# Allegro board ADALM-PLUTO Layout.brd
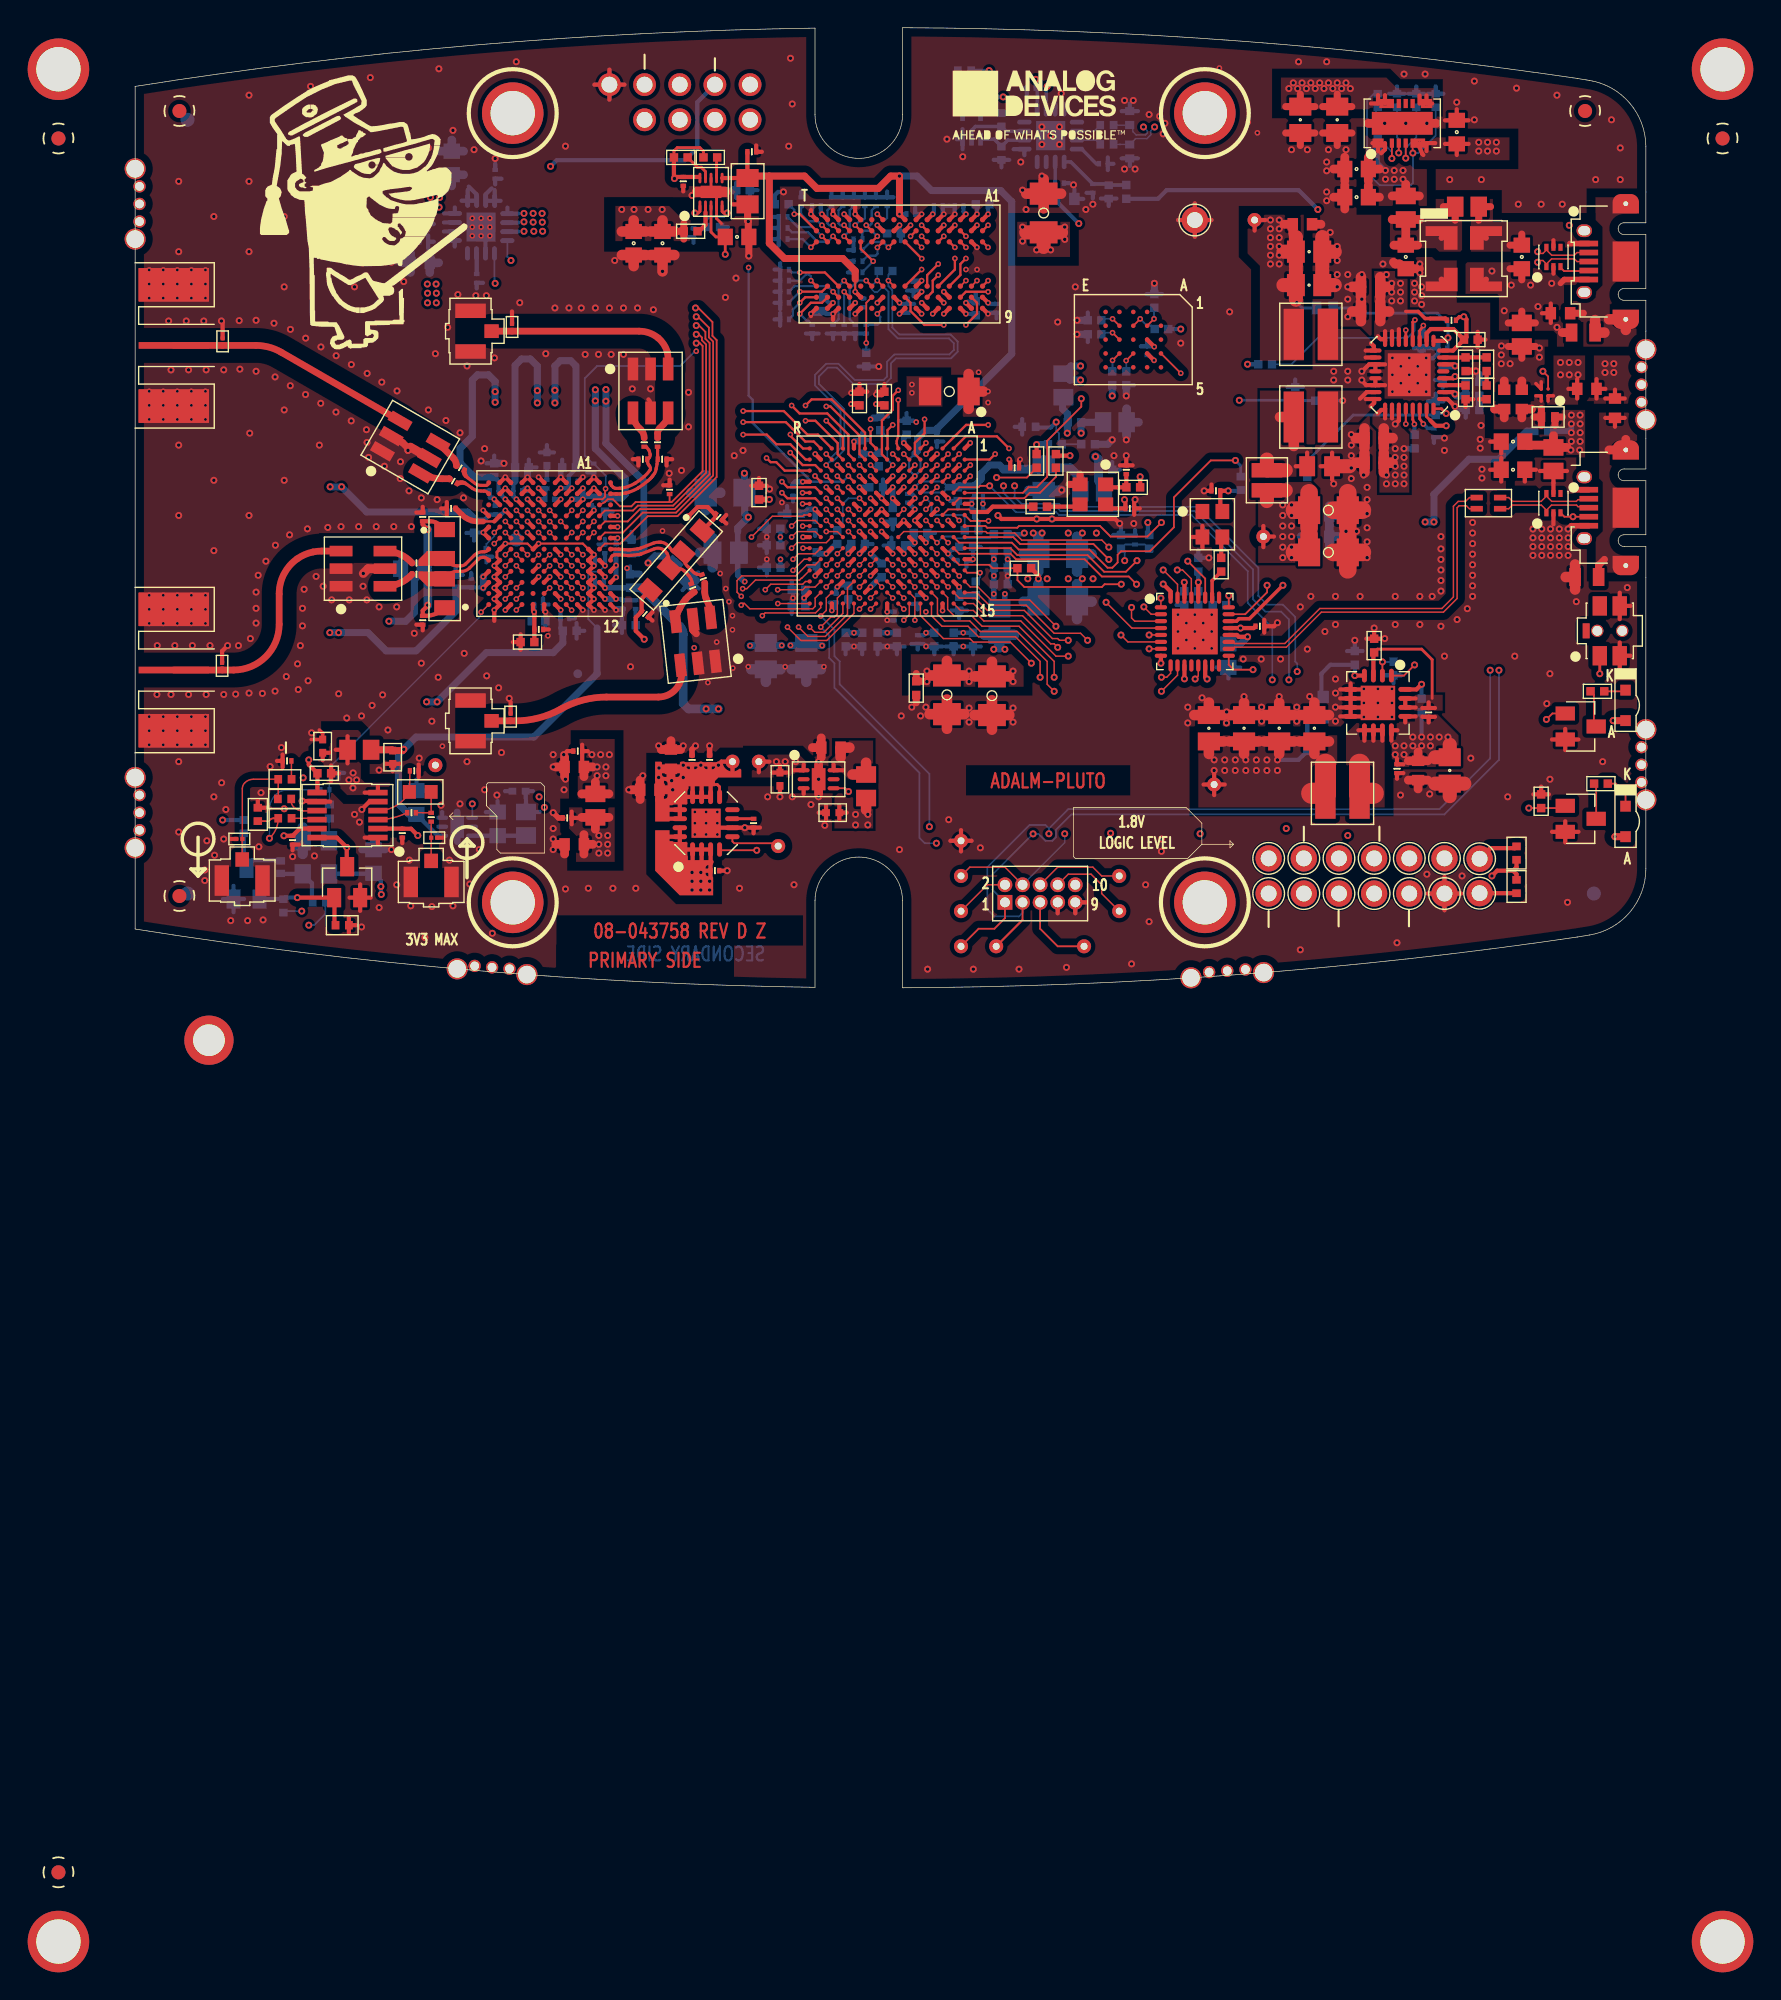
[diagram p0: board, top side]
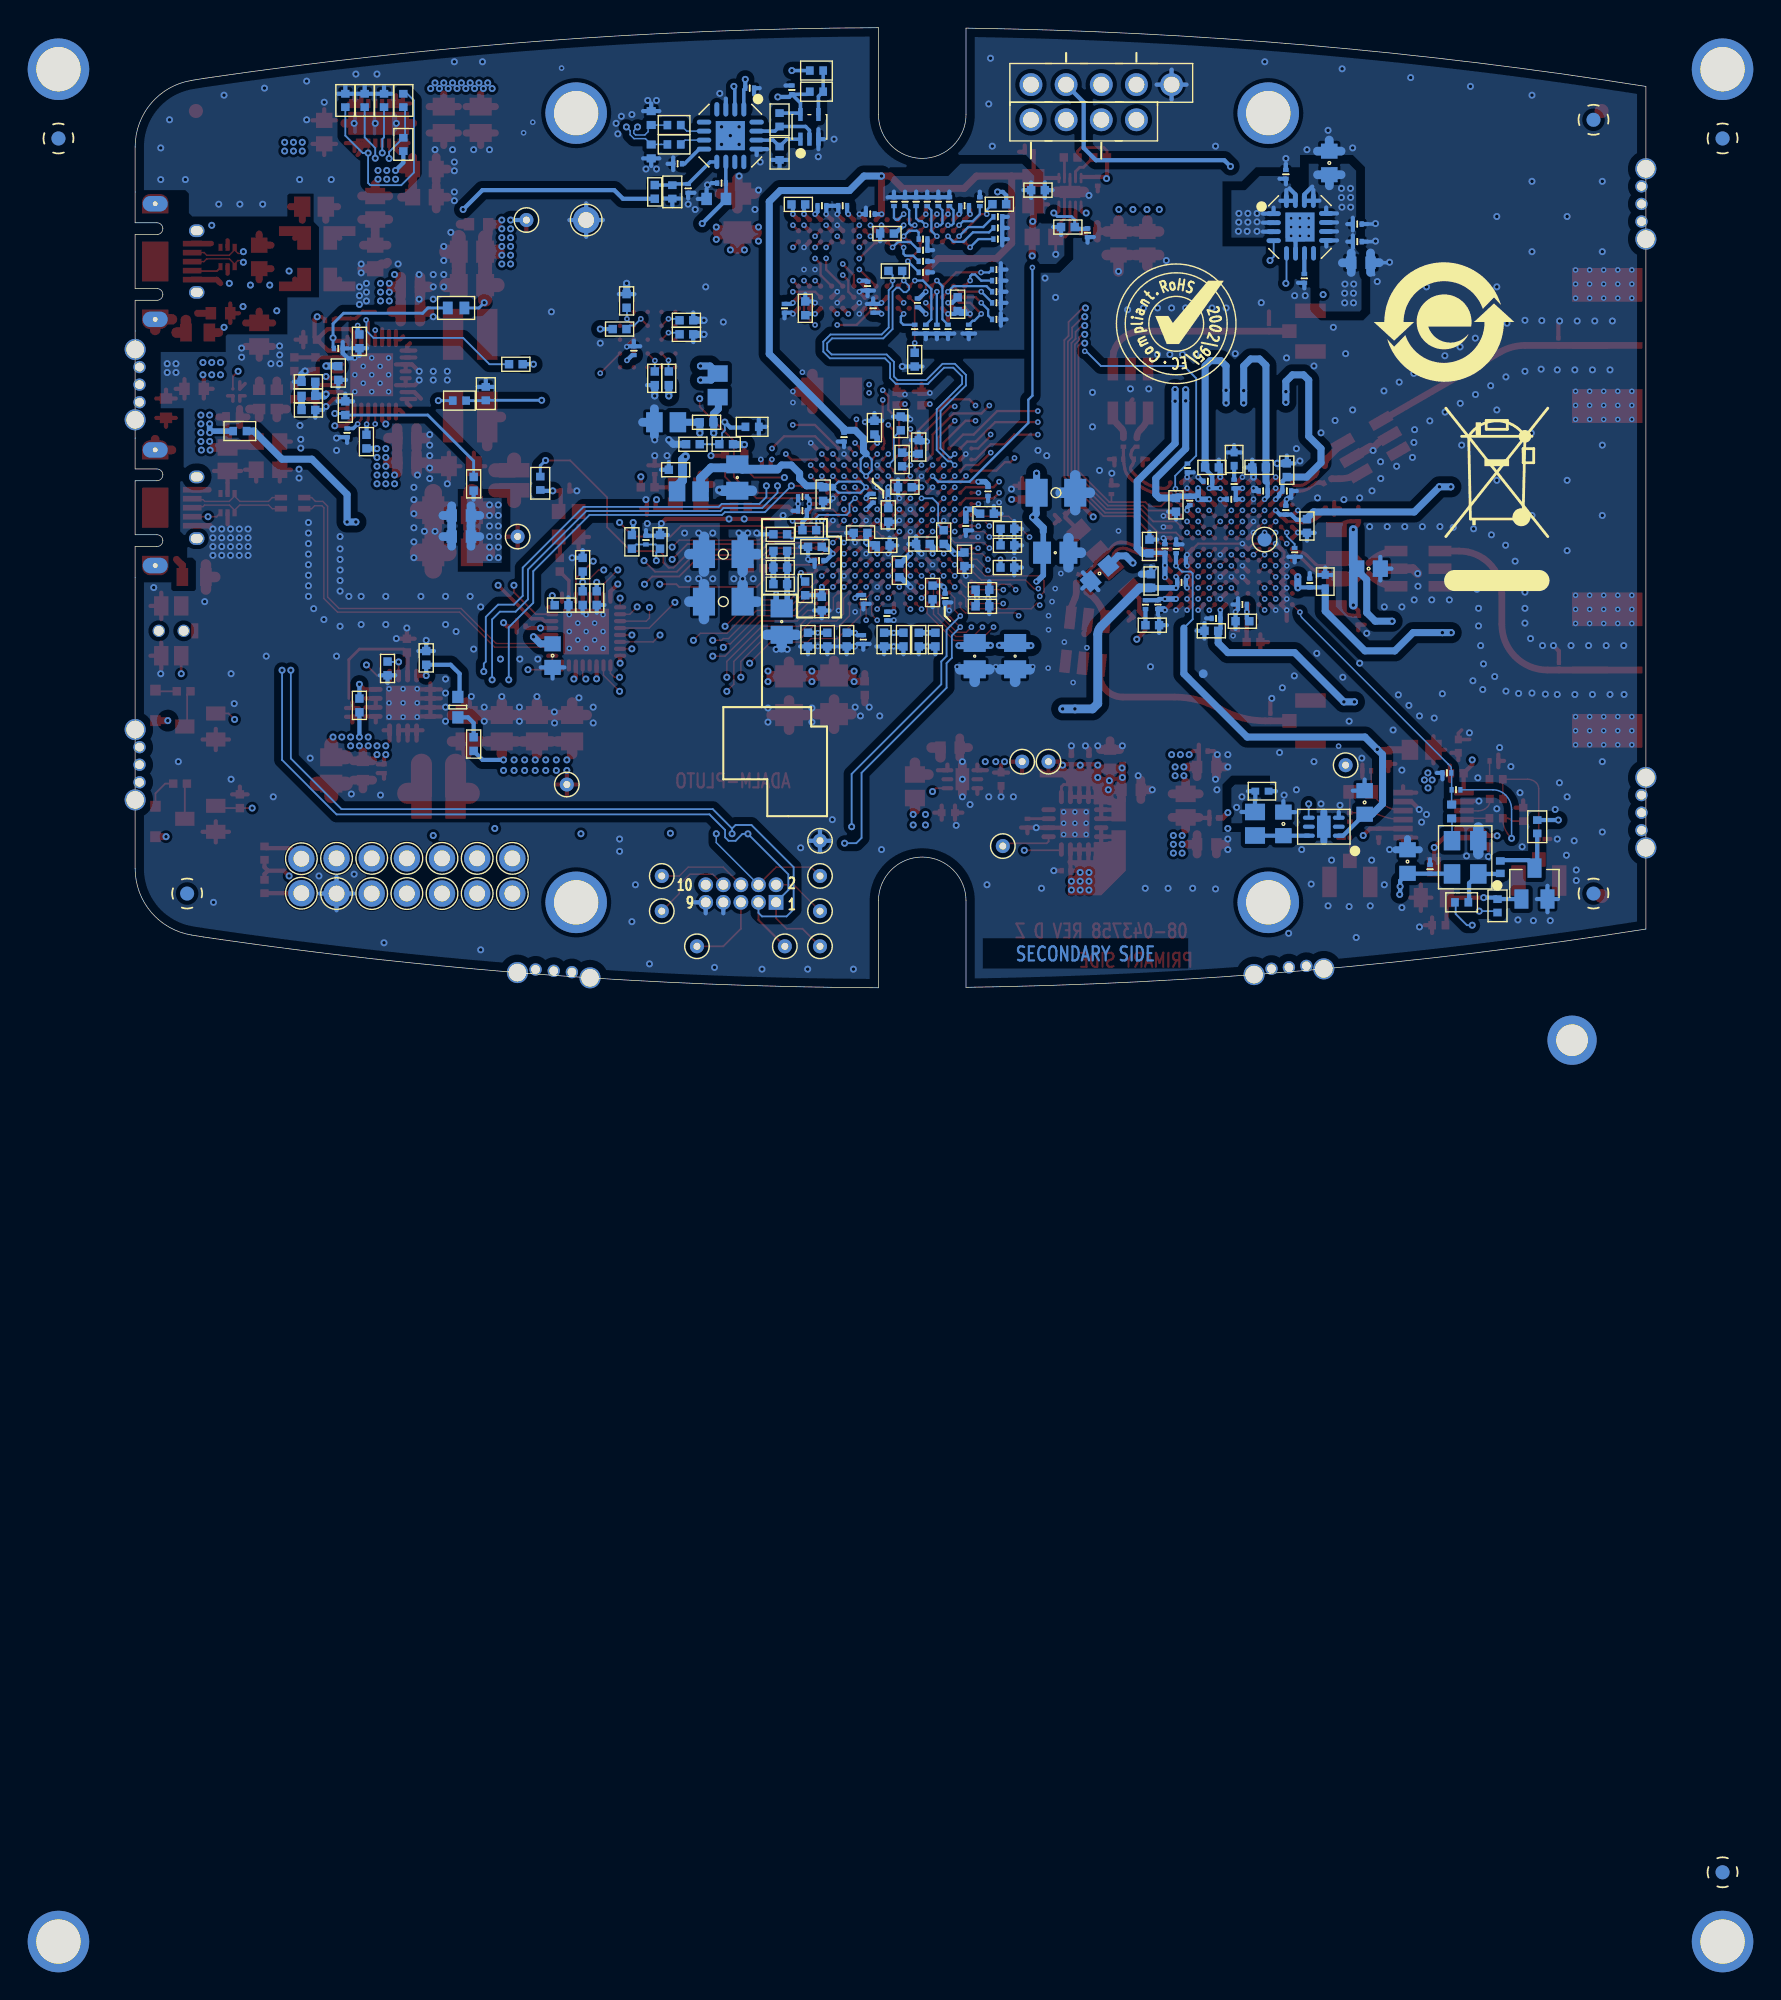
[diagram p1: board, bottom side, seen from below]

Outline 109.14 x 69.34 mm; copper layers: TOP, L2_GND, L3_PWR, L4_GND, L5_SIG, L6_SIG, L7_GND, L8_PWR, L9_GND, BOTTOM. Coordinates in mm from the lower left corner of the outline.
Outline path: 0,65.1 arc(24.48,68.08) 49.11,69.31 49.11,63.06 arc(52.28,59.9) 55.44,63.06 55.44,69.34 arc(79.87,68.37) 104.18,65.67 105.05,65.53 arc(107.98,63.88) 109.14,60.73 109.14,57.47 109.14,55.25 107.56,55.25 arc(107.26,55.12) 107.14,54.82 arc(107.26,54.52) 107.56,54.4 109.14,54.4 109.14,50.5 107.56,50.5 arc(107.26,50.37) 107.14,50.07 arc(107.26,49.77) 107.56,49.65 109.14,49.65 109.14,37.47 107.56,37.47 arc(107.26,37.34) 107.14,37.04 arc(107.26,36.74) 107.56,36.62 109.14,36.62 109.14,32.72 107.56,32.72 arc(107.26,32.59) 107.14,32.29 arc(107.26,31.99) 107.56,31.87 109.14,31.87 109.14,29.65 109.14,8.61 arc(107.98,5.45) 105.05,3.81 104.18,3.67 arc(79.87,0.97) 55.44,0 55.44,6.28 arc(52.28,9.44) 49.11,6.28 49.11,0.03 arc(24.48,1.26) 0,4.24 0,65.1

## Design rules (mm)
constraint set DEFAULT: min track width 0.127
net group DDR3_CK: nets DDR3_CK_N DDR3_CK_P
net group DDR3_DQS0: nets DDR3_DQS0_N DDR3_DQS0_P
net group DDR3_DQS1: nets DDR3_DQS1_N DDR3_DQS1_P
net group DP1: nets UNNAMED_9_CHOKE4P_I350_N2 UNNAMED_9_CHOKE4P_I350_N3
net group RX1A: nets RX1A_N RX1A_P
net group RX2A: nets RX2A_N RX2A_P
net group TX1A: nets TX1A_N TX1A_P
net group TX2A: nets TX2A_N TX2A_P
net group UART: nets UART_RX UART_TX
net group USB_OTG: nets USB_OTG_N USB_OTG_P
net group USB_UART: nets USB_UART_N USB_UART_P
net group CTRL_IN: nets CTRL_IN0 CTRL_IN1 CTRL_IN2 CTRL_IN3
net group CTRL_OUT: nets IO_L08_34_CTRL_OUT0 IO_L08_34_CTRL_OUT1 IO_L13_34_CTRL_OUT2 IO_L13_34_CTRL_OUT3 IO_L21_34_CTRL_OUT4 IO_L21_34_CTRL_OUT5 IO_L22_34_CTRL_OUT6 IO_L22_34_CTRL_OUT7
net group JTAG: nets JTAG_TCK JTAG_TDI JTAG_TDO JTAG_TMS
net group PWR: nets VCCPLL VDD33_USB VDDA1P1_RX_VCO VTTVREF
net group QSPI: nets PS_MIO01_500_QSPI0_SS_B PS_MIO02_500_QSPI0_IO0 PS_MIO03_500_QSPI0_IO1 PS_MIO04_500_QSPI0_IO2 PS_MIO05_500_QSPI0_IO3 PS_MIO06_500_QSPI0_SCLK
net group RF: nets UNNAMED_7_CAP_I57_N2 UNNAMED_7_CAP_I58_N2 UNNAMED_7_CAP_I85_N1 UNNAMED_7_CAP_I86_N1 UNNAMED_7_CAP_I116_N1 UNNAMED_7_CAP_I117_N1 UNNAMED_7_CAP_I118_N2 UNNAMED_7_CAP_I119_N2 UNNAMED_7_CNBNC3P_I43_CNTR UNNAMED_7_CNBNC3P_I74_CNTR UNNAMED_7_CNBNC5P_I64_CNTR UNNAMED_7_CNBNC5P_I83_CNTR
net group RX: nets IO_L01_34_RX_D0 IO_L01_34_RX_D1 IO_L02_34_RX_D2 IO_L02_34_RX_D3 IO_L03_34_RX_D4 IO_L03_34_RX_D5 IO_L04_34_RX_D6 IO_L04_34_RX_D7 IO_L05_34_RX_D8 IO_L05_34_RX_D9 IO_L06_34_RX_D10 IO_L06_34_RX_D11 IO_L07_34_RX_FRAME IO_L12_MRCC_34_DATA_CLK
net group SPI: nets IO_L23_35_SPI_CLK IO_L23_35_SPI_ENB IO_L24_35_SPI_DI IO_L24_35_SPI_DO
net group TX: nets IO_L01_34_FB_CLK IO_L09_34_TX_FRAME IO_L15_34_TX_D0 IO_L15_34_TX_D1 IO_L16_34_TX_D2 IO_L16_34_TX_D3 IO_L17_34_TX_D4 IO_L17_34_TX_D5 IO_L18_34_TX_D6 IO_L18_34_TX_D7 IO_L19_34_TX_D8 IO_L19_34_TX_D9 IO_L20_34_TX_D10 IO_L20_34_TX_D11
net group USB_ULPI: nets PS_MIO28_501_USB0_D4 PS_MIO29_501_USB0_DIR PS_MIO30_501_USB0_STP PS_MIO31_501_USB0_NXT PS_MIO32_501_USB0_D0 PS_MIO33_501_USB0_D1 PS_MIO34_501_USB0_D2 PS_MIO35_501_USB0_D3 PS_MIO36_501_USB0_CLK PS_MIO37_501_USB0_D5 PS_MIO38_501_USB0_D6 PS_MIO39_501_USB0_D7

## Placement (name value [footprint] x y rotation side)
AD9361_CLKOUT  TESTPAD  [TPSMC40]  27.55 32.37 180 bottom
ADC  613 001 111 21  [CNHDR1X1H344]  44.42 65.22 180 bottom
C1  0.1uF  [C0201]  26.01 58.75 89.8 bottom
C2  0.01uF  [C0201]  24.67 51.23 269.8 bottom
C3  10uF  [C0603#2]  22.87 59.57 89.8 bottom
C4  10uF  [C0603]  20.59 52.36 179.8 bottom
C5  0.1uF  [C0201]  20.85 53.88 179.8 bottom
C6  0.1uF  [C0201]  20.85 55.15 179.8 bottom
C7  0.1uF  [C0201]  93.83 40.08 90 bottom
C8  0.1uF  [C0201]  91.16 15.82 270 top
C9  10uF  [C0603]  92.68 15.69 270 top
C10  0.1uF  [C0201]  41.88 8.46 0 top
C11  47uF  [C0805H60]  94.97 15.69 270 top
C12  0.01uF  [C0201]  44.68 11.88 270 top
C13  0.1uF  [C0201#2]  89.51 24.71 90 top
C14  10uF  [C0603]  38.71 16.51 90 top
C15  10uF  [C0603]  37.18 14.3 180 top
C16  0.1uF  [C0201]  40.23 16.46 90 top
C17  47uF  [C0805H60]  82.65 18.74 90 top
C18  0.1uF  [C0201]  41.5 16.46 90 top
C19  47uF  [C0805H60]  77.57 18.74 90 top
C20  47uF  [C0805H60]  80.11 18.74 90 top
C21  47uF  [C0805H60]  85.19 18.74 90 top
C22  10uF  [C0603]  31.72 10.36 180 top
C23  0.01uF  [C0201]  31.65 36.58 0 bottom
C24  0.01uF  [C0201]  25.94 35.88 180 bottom
C25  0.1uF  [C0201]  31.21 12.27 180 top
C26  0.01uF  [C0201]  31.05 26.68 0 bottom
C27  0.01uF  [C0201]  34.75 31.72 90 bottom
C28  1UF  [C0402H22]  31.35 37.58 180 bottom
C29  1UF  [C0402H22]  25.94 37.38 90 bottom
C30  1UF  [C0402H22]  31.39 25.78 0 bottom
C31  1UF  [C0402H22]  35.86 31.87 90 bottom
C32  10uF  [C0603]  31.72 15.95 180 top
C33  0.1uF  [C0201]  31.98 17.09 180 top
C34  1UF  [C0402H22]  27.94 37.58 0 bottom
C35  1UF  [C0402H22]  35.75 29.38 90 bottom
C36  1UF  [C0402H22]  24.48 33.35 270 bottom
C37  1UF  [C0402H22]  33.95 34.88 270 bottom
C38  1UF  [C0402H22]  29.15 26.47 0 bottom
C39  0.01uF  [C0201]  27.64 35.88 0 bottom
C40  0.01uF  [C0201]  33.54 29.28 180 bottom
C41  0.01uF  [C0201]  26.01 34.49 90 bottom
C42  0.01uF  [C0201]  32.95 35.18 270 bottom
C43  0.01uF  [C0201]  29.16 25.88 0 top
C44  0.01uF  [C0201]  29.15 27.68 0 bottom
C45  1UF  [C0402H22]  28.34 24.97 180 top
C46  0.1uF  [C0201]  71.85 34.62 0 top
C47  0.1uF  [C0201]  72.24 32.33 90 bottom
C48  0.1uF  [C0201]  73.11 46.01 90 bottom
C49  100uF  [C1206H71]  66.65 31.32 0 bottom
C50  4.7uF  [C0402]  62.53 31.55 0 bottom
C51  0.47uF  [C0402]  47.6 34.24 180 bottom
C52  0.1uF  [C0201]  60.93 35.45 0 bottom
C53  0.01uF  [C0201]  60.93 34.45 0 bottom
C54  100uF  [C1206H71]  58.82 43.06 0 top
C55  4.7uF  [C0402]  55.73 40.45 90 bottom
C56  0.47uF  [C0402]  45.07 35.76 90 top
C57  0.47uF  [C0402]  54.13 42.55 90 top
C58  0.47uF  [C0402]  52.33 42.55 90 top
C59  0.47uF  [C0402]  52.53 39.05 90 bottom
C60  0.1uF  [C0201]  63.54 37.56 0 top
C61  0.01uF  [C0201]  47.52 35.85 270 bottom
C62  0.01uF  [C0201]  39.6 58.24 90 top
C63  0.01uF  [C0201]  56.03 55.88 180 bottom
C64  100uF  [C1206H71]  61.9 21.09 270 top
C65  47uF  [C0805H60]  48.49 23.95 270 bottom
C66  4.7uF  [C0402]  53.93 30.15 270 bottom
C67  4.7uF  [C0402]  52.53 25.14 270 bottom
C68  0.47uF  [C0402]  56.43 21.64 270 top
C69  0.47uF  [C0402]  60.03 31.85 0 bottom
C70  0.47uF  [C0402]  54.73 34.15 270 bottom
C71  100uF  [C1206H71]  58.65 21.16 270 top
C72  0.47uF  [C0402]  52.23 32.05 0 bottom
C73  4.7uF  [C0402]  53.53 36.15 0 bottom
C74  0.47uF  [C0402]  55.13 31.95 180 bottom
C75  0.47uF  [C0402]  56.73 32.85 0 bottom
C76  100uF  [C1206H71]  42.62 35.75 180 bottom
C77  47uF  [C0805H60]  42.67 31.42 180 bottom
C78  4.7uF  [C0402]  46.12 31.95 180 bottom
C79  10uF  [C0603#2]  43.48 54.23 0 top
C80  0.01uF  [C0201]  40.33 54.53 270 bottom
C81  0.22UF  [C0805H53]  44.25 57.53 270 top
C82  10uF  [C0603#2]  36.02 53.77 270 top
C83  10uF  [C0603#2]  38.1 53.77 270 top
C84  0.01uF  [C0201]  44.55 60.37 0 top
C85  47uF  [C0805H60]  65.64 36.85 270 bottom
C86  4.7uF  [C0402]  49.72 49.37 270 bottom
C87  4.7uF  [C0402]  60.73 49.07 90 bottom
C88  0.47uF  [C0402]  61.23 56.58 180 bottom
C89  0.47uF  [C0402]  54.82 54.47 0 bottom
C90  0.47uF  [C0402]  46.12 33.15 180 bottom
C91  0.1uF  [C0201]  55.82 49.07 90 bottom
C92  0.1uF  [C0201]  56.22 50.67 270 bottom
C93  0.47uF  [C0402]  67.86 40.84 0 bottom
C94  0.1uF  [C0201]  59.52 56.48 180 bottom
C95  0.1uF  [C0201]  58.02 56.48 0 bottom
C96  0.1uF  [C0201]  49.22 56.47 180 bottom
C97  0.1uF  [C0201]  62.23 49.07 270 bottom
C98  0.1uF  [C0201]  55.83 35.35 90 bottom
C99  0.01uF  [C0201]  57.92 39.76 90 bottom
C100  100uF  [C1206H71]  65.63 55.95 90 top
C101  4.7uF  [C0402]  43.91 57.6 180 bottom
C102  0.01uF  [C0201]  52.62 49.47 270 bottom
C103  47uF  [C0805H60]  62.43 26.44 270 bottom
C104  47uF  [C0805H60]  45.57 23.95 270 bottom
C105  4.7uF  [C0402]  55.03 25.14 270 bottom
C106  4.7uF  [C0402]  51.33 25.14 270 bottom
C107  4.7uF  [C0402]  60.53 25.14 270 bottom
C108  4.7uF  [C0402]  46.13 30.35 180 bottom
C109  0.47uF  [C0402]  53.63 25.14 270 bottom
C110  0.47uF  [C0402]  51.53 28.55 270 bottom
C111  0.47uF  [C0402]  59.53 27.74 270 bottom
C112  0.47uF  [C0402]  47.93 28.75 180 bottom
C113  0.47uF  [C0402]  59.13 25.14 270 bottom
C114  0.47uF  [C0402]  47.93 27.55 180 bottom
C115  0.47uF  [C0402]  57.74 25.14 270 bottom
C116  0.47uF  [C0402]  49.22 30.95 270 bottom
C117  0.1uF  [C0201]  56.53 25.14 270 bottom
C118  0.1uF  [C0201]  50.63 28.15 270 bottom
C119  0.01uF  [C0201]  54.83 26.85 270 bottom
C120  0.01uF  [C0201]  49.13 33.35 270 bottom
C121  10uF  [C0603#2]  17.22 9.12 90 bottom
C122  0.1uF  [C0201]  15.59 8.56 90 bottom
C123  1UF  [C0402H22]  27.74 14.2 180 bottom
C124  18PF  [C0201]  14.37 15.52 0 bottom
C125  0.001uF  [C0201]  29.94 35.28 180 bottom
C126  1UF  [C0402H22]  29.74 38.18 270 bottom
C127  1UF  [C0402H22]  35.66 26.18 179.9 bottom
C128  0.001uF  [C0201]  35.25 27.67 270 bottom
C129  0.001uF  [C0201]  20.78 26.54 90 top
C130  18PF  [C0201]  41.04 29.54 289.4 top
C131  18PF  [C0201]  20.32 29.86 180 top
C132  18PF  [C0201]  20.32 30.67 180 top
C133  18PF  [C0201]  22.98 36.59 330 top
C134  18PF  [C0201]  23.49 37.55 330 top
C135  10uF  [C0603]  89.51 39.7 180 top
C136  10uF  [C0603]  89.25 48.84 180 top
C137  10uF  [C0603]  89.51 37.92 180 top
C138  10uF  [C0603]  89.25 50.62 180 top
C139  0.047UF  [C0402]  92.94 46.68 90 bottom
C140  1UF  [C0402H22]  76.81 30.55 90 bottom
C141  1UF  [C0402H22]  96.49 46.81 0 top
C142  150pF  [C0402]  96.62 43.76 180 bottom
C143  180PF  [C0402]  96.11 45.03 90 top
C144  0.0033uF  [C0402]  97.64 45.03 270 top
C145  47uF  [C0805H60]  84.81 53.16 0 top
C146  22UF  [C0805]  85.57 37.67 0 top
C147  5.6NF  [C0402H22]  96.62 41.73 0 bottom
C148  47uF  [C0805H60]  84.81 50.75 0 top
C149  100uF  [C1206H71]  86.21 31.44 0 top
C150  100uF  [C1206H71]  86.21 34.49 0 top
C151  10uF  [C0603]  84.33 55.14 0 top
C152  10uF  [C0603]  85.57 34.11 0 bottom
C153  10uF  [C0603]  85.57 32.59 0 bottom
C154  1UF  [C0402H22]  75.79 28.14 270 bottom
C155  10uF  [C0603#2]  20.03 30.27 180 bottom
C156  18PF  [C0201]  40.28 28.88 290.2 top
C157  18PF  [C0201]  13.71 14.3 0 bottom
C158  100uF  [C1206H71]  66.65 27.89 0 bottom
C159  4.7uF  [C0402]  62.53 30.35 0 bottom
C160  0.47uF  [C0402]  62.53 29.15 0 bottom
C161  0.1uF  [C0201]  56.53 28.05 270 bottom
C162  0.01uF  [C0201]  59.73 30.85 0 bottom
C163  0.1uF  [C0201]  78.08 35.89 0 top
C164  0.1uF  [C0201]  81.25 26.11 0 top
C165  2.2UF  [C0603#2]  78.98 23.99 270 bottom
C166  0.001uF  [C0201]  42.16 34.01 139 top
C167  10uF  [C0603#2]  39.47 29.92 318.8 bottom
C168  1UF  [C0402H22]  76.81 28.14 270 bottom
C169  1UF  [C0402H22]  50.39 12.65 180 top
C170  1UF  [C0402H22]  46.58 15.06 270 top
C171  2.2UF  [C0603]  98.91 42.49 90 top
C172  2.2UF  [C0603]  100.18 42.49 90 top
C173  10uF  [C0603]  50.26 17.35 180 top
C174  4.7uF  [C0402]  70.09 37.41 0 bottom
C175  18PF  [C0201]  36.78 39.39 270 top
C176  18PF  [C0201]  37.74 39.39 270 top
C177  0.1UF  [C0603]  106.91 41.86 270 top
C178  0.47uF  [C0402]  59.44 35.65 270 bottom
C179  0.01uF  [C0201]  21.39 12.32 90 top
C180  0.01uF  [C0201]  20.17 15.67 0 top
C181  0.1UF  [C0603]  102.97 48.71 0 top
C182  2.2UF  [C0603]  104.87 43.25 0 top
C183  0.1UF  [C0603#2]  99.54 39.44 180 top
C184  47uF  [C0805H60]  86.84 62.68 270 top
C185  47uF  [C0805H60]  84.17 62.68 270 top
C186  0.1uF  [C0201]  64.74 64.97 180 bottom
C187  0.01uF  [C0201]  69.19 57.73 270 bottom
C188  0.1uF  [C0201]  66.77 58.11 0 bottom
C189  0.1uF  [C0201]  69.95 59.51 0 bottom
C190  0.1uF  [C0201]  61.69 64.84 90 bottom
C191  0.01uF  [C0201]  24.28 29.23 90 bottom
C192  1UF  [C0402H22]  23.16 29.33 90 bottom
C193  0.001uF  [C0201]  36.83 27 138.4 top
C194  0.001uF  [C0201]  20.78 34.01 270 top
C195  10uF  [C0603#2]  26.19 11.83 90 bottom
C196  47pF  [C0402]  71.85 60.4 90 bottom
C197  47pF  [C0402]  71.85 62.81 270 bottom
C198  2.2UF  [C0603#2]  20.32 13.38 90 bottom
C199  1UF  [C0402H22]  18.61 16.65 270 top
C200  1UF  [C0402H22]  13.55 17.45 90 top
C201  0.1uF  [C0201]  11.37 10.66 270 top
C202  0.1uF  [C0201]  19.3 11.17 270 top
C203  0.1uF  [C0201]  33.93 31.7 90 bottom
C204  47pF  [C0402]  14.03 12.73 90 bottom
C205  0.01uF  [C0201]  10.97 16.38 180 top
C206  0.1uF  [C0201]  38.61 35.97 90 top
C207  0.001uF  [C0201]  25.37 31.44 90 bottom
C208  0.1uF  [C0201]  33.12 37.54 270 bottom
C209  10uF  [C0603#2]  88.24 59.13 180 top
C210  2.2UF  [C0603#2]  95.48 61.8 90 top
C211  0.1UF  [C0603#2]  99.54 37.41 180 top
C212  0.1UF  [C0603#2]  88.24 57.1 180 top
C213  0.1UF  [C0603#2]  91.79 52.78 270 top
C214  0.1UF  [C0603#2]  100.18 52.78 270 top
C215  2.2UF  [C0603]  67.16 56.97 0 bottom
CLK_IN  U.FL-R-SMT-1(01)  [CNHIROSE-U_FL-R-SMT-1]  21.39 7.64 180 top
CLK_OUT  U.FL-R-SMT-1(01)  [CNHIROSE-U_FL-R-SMT-1]  7.73 7.74 180 top
D1  SP3004-04XTG  [SOT-563]  102.46 35 0 top
D2  SP3004-04XTG  [SOT-563]  102.46 52.78 0 top
D3  ESD8472MUT5G  [DFN2_0_62X0_32]  27.23 47.72 270 top
D4  ESD8472MUT5G  [DFN2_0_62X0_32]  6.32 46.68 270 top
D7  ESD8472MUT5G  [DFN2_0_62X0_32]  21.61 10.84 180 top
D8  ESD8472MUT5G  [DFN2_0_62X0_32]  7.53 10.75 0 top
D9  ESD8472MUT5G  [DFN2_0_62X0_32]  6.28 23.25 270 top
D10  ESD8472MUT5G  [DFN2_0_62X0_32]  27.13 19.58 270 top
DAC1  613 001 111 21  [CNHDR1X1H344]  36.8 65.22 180 bottom
DAC2  613 001 111 21  [CNHDR1X1H344]  36.8 62.68 180 bottom
DS1  LTST-S220TBKT  [LED0804]  107.67 20.39 270 top
DS2  LTST-S220TBKT  [LED0804]  107.67 12.01 270 top
E1  100OHM  [L0805]  69.14 35.85 180 bottom
E2  100OHM  [L0805]  52.8 14.55 90 top
E3  600OHM AT 100MEGHZ  [L0805]  102.46 38.17 270 top
E4  100OHM  [L0805]  33.25 13.15 90 top
E5  100OHM  [L0805]  67.05 43.51 270 bottom
E6  100OHM  [L0805]  70.78 40.84 180 bottom
E7  100OHM  [L0805]  28.24 11.85 270 bottom
E8  100OHM  [L0805]  16.19 17.19 180 top
E9  600OHM AT 100MEGHZ  [L0805]  91.79 56.33 270 top
E10  600OHM AT 100MEGHZ  [L0805]  100.18 47.17 90 top
E11  600OHM AT 100MEGHZ  [L0805]  96.21 56.41 0 top
F1  0.5A  [F0402H20]  102.08 41.22 0 top
GND  613 001 111 21  [unnamed#3]  34.26 65.22 180 bottom
GND#2  WP45  [unnamed#3]  94.59 6.8 180 bottom
GND#3  WP45  [unnamed#3]  76.55 55.45 180 bottom
GND#4  TESTPAD  [unnamed#3]  59.66 10.61 180 bottom
GPO0  613 001 111 21  [CNHDR1X1H344]  44.42 62.68 180 bottom
GPO1  613 001 111 21  [CNHDR1X1H344]  41.88 62.68 180 bottom
GPO2  613 001 111 21  [CNHDR1X1H344]  39.34 62.68 180 bottom
GPO3  613 001 111 21  [CNHDR1X1H344]  39.34 65.22 180 bottom
JTAG_BOOT  TESTPAD  [TPSMC40]  68.55 2.99 180 bottom
L1  330NH  [L0805-F]  40.28 32.22 228.6 top
L2  1.5uH  [LSMSQ157H83]  84.94 47.19 180 top
L3  1.5uH  [LSMSQ157H83]  84.94 41.22 180 top
L4  1uH  [LSMSQ157H83]  87.22 14.04 180 top
L5  270NH  [LSMSQ79H41]  81.76 36.65 270 top
L6  90OHMS AT 100MEGHZ  [L0805-4PH39]  97.76 35 0 top
L7  330NH  [L0805-F]  37.9 29.51 48.8 top
L7N  WP45  [TPC75D45]  97.13 9.32 0 top
L8  330NH  [L0805-F]  22.36 28.49 90 top
L9  330NH  [L0805-F]  22.36 32.05 270 top
L9N  WP45  [TPC75D45]  97.13 6.83 0 top
L10  800OHMS AT 100MEGHZ  [L2020_A]  95.98 52.65 180 top
L10P  WP45  [TPC75D45]  81.89 6.8 180 bottom
L12N  WP45  [TPC75D45]  84.43 6.8 180 bottom
L24N  WP45  [TPC75D45]  81.89 9.34 180 bottom
MIO0  WP45  [TPC75D45]  92.05 9.34 180 bottom
MIO09  WP45  [TPC75D45]  89.51 6.8 180 bottom
MIO10  WP45  [TPC75D45]  92.05 6.8 180 bottom
MIO11  WP45  [TPC75D45]  89.51 9.34 180 bottom
MIO48  WP45  [TPC75D45]  84.43 9.34 180 bottom
MIO49  WP45  [TPC75D45]  86.97 6.8 180 bottom
MIO53  WP45  [TPC75D45]  86.97 9.34 180 bottom
NOREF  -  [unnamed]  108.82 43.56 0 top
NOREF#2  -  [unnamed]  76.28 0.72 0 top
NOREF#3  -  [#2]  114.68 -68.88 0 top
NOREF#4  -  [unnamed]  -5.54 -68.88 180 top
NOREF#5  -  [#2]  -8.54 -71.88 0 top
NOREF#6  -  [unnamed]  0.32 57.88 0 top
NOREF#7  -  [#2]  64.97 63.73 0 top
NOREF#8  -  [unnamed]  0 15.18 0 top
NOREF#9  -  [#2]  0 -67.64 0 top
NOREF#10  -  [unnamed]  108.82 42.29 0 top
NOREF#11  -  [#2]  -8.54 69.34 0 top
NOREF#12  -  [#2]  -1.27 -61.78 0 top
NOREF#13  -  [#2]  -1.27 -56.7 0 top
NOREF#14  -  [unnamed]  114.68 -68.88 180 top
NOREF#15  -  [#2]  -5.54 66.34 0 top
NOREF#16  -  [unnamed]  0.32 12.64 0 top
NOREF#17  -  [unnamed]  0.32 55.34 0 top
NOREF#18  -  [unnamed]  0.32 13.91 0 top
NOREF#19  -  [unnamed]  0.32 56.61 0 top
NOREF#20  -  [unnamed]  -5.54 66.34 180 top
NOREF#21  -  [unnamed]  -5.54 -63.88 0 top
NOREF#22  -  [#2]  117.68 -71.88 90 top
NOREF#23  -  [unnamed]  77.59 1.13 0 top
NOREF#24  -  [unnamed]  108.82 17.38 0 top
NOREF#25  -  [unnamed]  3.2 63.32 0 top
NOREF#26  -  [#2]  -1.27 54.07 0 top
NOREF#27  -  [#2]  -1.27 10.1 0 top
NOREF#28  -  [#2]  11.73 -2.58 0 top
NOREF#29  -  [unnamed]  104.75 63.32 0 top
NOREF#30  -  [unnamed]  108.82 16.11 0 top
NOREF#31  -  [#2]  -1.27 15.18 0 top
NOREF#32  -  [unnamed]  27.28 6.17 180 top
NOREF#33  -  [unnamed]  109.14 18.65 0 top
NOREF#34  -  [unnamed]  -5.54 61.34 0 top
NOREF#35  -  [unnamed]  109.14 41.02 0 top
NOREF#36  -  [#2]  -99.72 -146.23 0 top
NOREF#37  -  [#2]  226.68 44.12 0 top
NOREF#38  -  [unnamed]  28.3 0.95 0 top
NOREF#39  -  [#2]  -99.72 -146.23 0 top
NOREF#40  -  [#2]  111.68 -71.88 0 top
NOREF#41  -  [#2]  -1.27 -17.81 0 top
NOREF#42  -  [#2]  117.68 -71.88 0 top
NOREF#43  -  [#2]  115.99 67.29 0 top
NOREF#44  -  [#2]  -37.76 235.07 0 top
NOREF#45  -  [unnamed]  0 10.1 0 top
NOREF#46  -  [unnamed]  108.82 14.84 0 top
NOREF#47  -  [#2]  -1.27 59.15 0 top
NOREF#48  -  [#2]  115.67 61.49 0 top
NOREF#49  -  [#2]  -5.54 -68.88 0 top
NOREF#50  -  [unnamed]  77.28 6.17 180 top
NOREF#51  -  [unnamed]  0 54.07 0 top
NOREF#52  -  [unnamed]  23.27 1.36 0 top
NOREF#53  -  [unnamed]  114.68 61.34 0 top
NOREF#54  -  [#2]  -99.72 -146.23 0 top
NOREF#55  -  [unnamed]  108.82 44.83 0 top
NOREF#56  -  [unnamed]  3.2 6.63 0 top
NOREF#57  -  [unnamed]  0 59.15 0 top
NOREF#58  -  [#2]  394.55 166.11 0 top
NOREF#59  -  [#2]  10.89 57.99 0 top
NOREF#60  -  [unnamed]  109.14 13.57 0 top
NOREF#61  -  [#2]  109.14 -63.28 0 top
NOREF#62  -  [#2]  -1.27 -12.73 0 top
NOREF#63  -  [unnamed]  0.32 11.37 0 top
NOREF#64  -  [unnamed]  27.28 63.17 180 top
NOREF#65  -  [#2]  28.04 49.35 0 top
NOREF#66  -  [#2]  -8.54 69.34 0 top
NOREF#67  -  [unnamed]  80.21 1.32 0 top
NOREF#68  -  [unnamed]  114.68 66.34 180 top
NOREF#69  -  [unnamed]  81.52 1.1 0 top
NOREF#70  -  [#2]  95.96 -2.55 0 top
NOREF#71  -  [#2]  -88.72 16.63 0 top
NOREF#72  -  [#2]  -2.54 -71.88 0 top
NOREF#73  -  [unnamed]  25.79 1.48 0 top
NOREF#74  -  [unnamed]  77.28 63.17 180 top
NOREF#75  -  [unnamed]  27.04 1.37 0 top
NOREF#76  -  [unnamed]  109.14 46.1 0 top
NOREF#77  -  [unnamed]  78.9 1.23 0 top
NOREF#78  -  [#2]  -8.54 -71.88 0 top
NOREF#79  -  [unnamed]  5.33 -3.79 0 top
NOREF#80  -  [unnamed]  24.53 1.58 0 top
NOREF#81  -  [#2]  -5.54 -68.88 0 top
NOREF#82  -  [unnamed]  105.38 6.8 180 bottom
NOREF#83  -  [unnamed]  3.78 6.8 180 bottom
NOREF#84  -  [unnamed]  -5.54 61.34 180 bottom
NOREF#85  -  [unnamed]  114.68 61.34 180 bottom
NOREF#86  -  [unnamed]  -5.54 -63.88 180 bottom
NOREF#87  -  [#2]  33.93 47.95 180 bottom
NOREF#88  -  [#2]  1.5 45.54 180 bottom
NOREF#89  -  [unnamed]  3.78 62.68 180 bottom
NOREF#90  -  [#2]  14.58 48.08 180 bottom
P1  FTSH-105-01-L-D  [CNHDR2X5H219]  62.84 6.17 0 top
P2  47590-0001  [CNMOLEX47590-0001]  109.14 34.67 180 top
P3  47590-0001  [CNMOLEX47590-0001]  109.14 52.45 180 top
PG_1P3V  TESTPAD  [TPSMC40]  46.45 10.23 180 bottom
Q1  BSS138LT1G  [SOT23]  104.43 18.87 270 top
Q2  BSS138LT1G  [SOT23]  8.05 7.53 180 bottom
Q3  BSS138LT1G  [SOT23]  15.32 7.63 0 top
Q4  BSS138LT1G  [SOT23]  104.43 12.2 270 top
R1  10  [R0201]  93.44 19.89 270 top
R2  27.4K  [R0402]  88.11 23.82 270 bottom
R3  46.4K  [R0402]  90.9 23.06 90 bottom
R4  17.8K  [R0603]  85.82 20.27 270 bottom
R5  1K  [R0402]  13.31 6.17 180 bottom
R6  10K  [R0402]  92.94 20.39 90 bottom
R7  1K  [R0402]  84.68 17.6 270 bottom
R8  10K  [R0402]  72.11 36.14 180 top
R9  10K  [R0201]  71.6 37.41 90 top
R10  0  [R0201]  19.96 12.65 180 top
R11  4.7K  [R0402]  66.44 39.25 0 bottom
R12  39  [R0402]  65.38 34.74 180 top
R13  20K  [R0402]  73.25 32.2 270 bottom
R14  240  [R0402]  74.14 47.57 180 bottom
R15  0  [R0402]  71.22 32.2 90 bottom
R16  120  [R0201]  51.92 56.77 90 bottom
R17  120  [R0201]  46.82 54.88 180 bottom
R18  120  [R0201]  46.91 50.27 180 bottom
R19  120  [R0201]  48.92 47.57 270 bottom
R20  120  [R0201]  46.92 48.27 180 bottom
R21  120  [R0201]  52.02 47.57 270 bottom
R22  120  [R0201]  46.92 51.87 180 bottom
R23  120  [R0201]  51.12 56.77 90 bottom
R24  120  [R0201]  50.32 56.77 90 bottom
R25  120  [R0201]  48.12 56.77 90 bottom
R26  120  [R0201]  46.82 55.68 180 bottom
R27  120  [R0201]  46.91 49.47 180 bottom
R28  120  [R0201]  50.42 47.57 270 bottom
R29  120  [R0201]  46.92 51.07 180 bottom
R30  120  [R0201]  51.22 47.57 270 bottom
R31  120  [R0201]  52.22 54.07 180 bottom
R32  120  [R0201]  52.22 52.47 180 bottom
R33  120  [R0201]  54.32 56.77 90 bottom
R34  120  [R0201]  46.82 54.07 180 bottom
R35  120  [R0201]  52.72 56.77 90 bottom
R36  120  [R0201]  52.22 51.67 180 bottom
R37  120  [R0201]  52.22 53.27 180 bottom
R38  120  [R0201]  52.82 47.57 270 bottom
R39  120  [R0201]  53.52 56.77 90 bottom
R40  240  [R0402]  53.83 40.75 90 bottom
R41  240  [R0402]  53.73 38.15 90 bottom
R42  1K  [R0402]  46.71 56.59 180 bottom
R43  0  [R0402]  41.76 54.94 180 bottom
R44  0  [R0402]  40.13 54.63 0 top
R45  0  [R0402]  60.43 33.05 180 bottom
R46  4.7K  [R0402]  50.73 32.55 270 bottom
R47  4.7K  [R0402]  65.12 38.05 90 top
R48  470  [R0402]  105.64 21.41 180 top
R49  14.3K  [R0201]  22.83 34.62 0 top
R50  100K  [R0402]  81.63 45.03 180 bottom
R51  1  [R0201]  29.74 36.38 270 bottom
R52  1  [R0201]  36.15 27.67 270 bottom
R53  27.4K  [R0402]  96.11 43 90 top
R54  4.7K  [R0402]  94.46 44.4 270 bottom
R55  1K  [R0805]  104.87 29.66 180 top
R56  10  [R0201]  95.1 48.21 0 top
R57  20K  [R0402]  79.87 36.43 90 bottom
R58  1K  [R0805]  104.62 47.32 180 top
R59  100K  [R0402]  92.43 39.44 270 bottom
R60  10K  [R0402]  96.62 42.75 0 bottom
R61  10K  [R0402]  97.64 43 90 top
R62  17.8K  [R0603#2]  85.95 49.1 0 bottom
R63  14.3K  [R0201]  94.46 46.17 180 bottom
R64  46.4K  [R0402]  84.68 36.4 270 bottom
R65  23.2K  [R0402]  93.95 41.86 270 bottom
R66  20K  [R0402]  64.57 40.51 0 bottom
R67  1K  [R0402]  10.51 8.71 90 bottom
R68  2.2K  [R0402]  99.79 7.31 270.1 top
R69  0  [R0201]  36.68 38.17 0.1 top
R70  27.4K  [R0402]  89.76 60.91 90 bottom
R71  100  [R0402]  89.76 64.08 90 bottom
R72  8.06K  [R0402]  93.95 64.08 90 bottom
R73  470  [R0402]  92.56 64.08 90 bottom
R74  10K  [R0402]  64.23 30.3 180 top
R75  10K  [R0402]  101.57 13.47 90 top
R76  20K  [R0402]  60.73 28.84 90 bottom
R77  8.06K  [R0402]  78.33 27.63 180 bottom
R78  470  [R0402]  91.16 64.08 270 bottom
R79  39  [R0402]  70.2 60.91 180 bottom
R80  4.7K  [R0402]  71.6 57.48 90 bottom
R81  39  [R0402]  70.2 62.3 180 bottom
R82  39  [R0402]  78.46 30.55 90 top
R83  20K  [R0402]  62.53 32.75 180 bottom
R84  20K  [R0402]  66.52 38.05 90 top
R85  4.7K  [R0402]  13.66 15.49 180 top
R86  240  [R0402]  10.82 12.24 180 top
R87  470  [R0402]  105.89 14.74 180 top
R88  24.9K  [R0402]  101.57 40.21 180 bottom
R89  4.7K  [R0402]  85.71 42.4 180 bottom
R90  4.7K  [R0402]  83.81 42.91 90 bottom
R91  4.7K  [R0402]  68.84 39.25 0 bottom
R92  10K  [R0402]  70.33 57.48 270 bottom
R93  10K  [R0402]  62.58 60.27 270 bottom
R94  10K  [R0402]  59.92 64.72 180 bottom
R95  39  [R0402]  59.92 66.24 0 bottom
R96  49.9  [R0603H18]  20.6 14.15 180 top
R97  2.2K  [R0402]  99.79 9.73 90 top
R98  75  [R0402]  10.79 13.64 180 top
R99  240  [R0402]  8.86 12.52 90 top
R100  100  [R0402]  10.82 15.06 180 top
R101  2.2K  [R0402]  7.85 11.63 270 bottom
R102  39  [R0402]  10.72 5.92 270 bottom
R103  2.2K  [R0402]  14.96 4.52 0 top
R104  0  [R0201]  38.07 38.17 180 top
R107  10K  [R0402]  62.58 62.68 270 bottom
R116  20K  [R0402]  73.63 49.6 90 bottom
R119  20K  [R0402]  69.31 48.21 180 bottom
R120  20K  [R0402]  69.31 47.19 180 bottom
R121  20K  [R0402]  71.6 44.02 270 bottom
R122  20K  [R0402]  70.58 44.02 270 bottom
R142  80.6  [R0402]  54.22 51.77 180 bottom
R165  240  [R0402]  52.82 45.36 270 bottom
R221  10K  [R0402]  39.42 59.97 0 top
R222  10K  [R0402]  41.55 59.97 0 top
RX  TESTPAD  [TPSMC40]  59.66 2.99 180 bottom
RX1A  JCCEM001  [CNSMARAL687W375H171]  2.54 46.39 180 top
RX2A  U.FL-R-SMT-1(01)  [CNHIROSE-U_FL-R-SMT-1]  24.23 47.42 90 top
S1  PTS840 GKP SMTR LFS  [SWSML140W138H55]  106.53 25.78 0 top
T1  TCM1-63AX+  [TSML150W160H160]  19.88 39.05 60 top
T2  TCM1-63AX+  [TSML150W160H160]  37.23 43.1 0 top
T3  TCM1-63AX+  [TSML150W160H160]  40.49 25.02 186.3 top
T5  TCM1-63AX+  [TSML150W160H160]  16.46 30.27 90 top
TCK  TESTPAD  [TPSMC40]  59.66 8.07 180 bottom
TDI  TESTPAD  [TPSMC40]  71.09 5.53 180 bottom
TDO  TESTPAD  [TPSMC40]  71.09 8.07 180 bottom
TMS  TESTPAD  [TPSMC40]  59.66 5.53 180 bottom
TX  TESTPAD  [TPSMC40]  62.2 2.99 180 bottom
TX1A  JCCEM001  [CNSMARAL687W375H171]  2.54 22.95 180 top
TX2A  U.FL-R-SMT-1(01)  [CNHIROSE-U_FL-R-SMT-1]  24.23 19.28 90 top
U1  ADP1754ACPZ-1.3  [QFN16_4X4_PAD2_1X2_1]  24.99 54.94 269.8 bottom
U2  MT41K256M16TW-107 IT:P  [FBGA96_C]  55.22 52.27 180 top
U3  ADP2164ACPZ  [QFN16_4X4_PAD2_5X2_5]  89.78 20.57 180 top
U4  XC7Z010-1CLG225C4334  [CSPBGA225]  54.33 33.35 180 top
U5  AD9363ABCZ  [BGA144-2]  29.94 32.08 180 top
U6  ADP2114ACPZ  [QFN32_5X5_PAD3_1X3_1]  92.05 44.27 90 top
U7  ADP1754ACPZ-1.3  [QFN16_4X4_PAD2_1X2_1]  41.25 11.88 0 top
U8  LTC4415EDHC#PBF  [DFN16_5X3_PAD4_4X1_65]  91.54 62.43 0 top
U9  FT230XQ-R  [QFN16_4X4_PAD2_1X2_1]  66.14 61.54 0 bottom
U10  74LVC1G126GW  [SOT353]  60.42 62.18 180 bottom
U11  ADM7160ACPZN3.3  [DFN6_2X2_PAD1_6X1]  23.26 11.63 90 bottom
U12  ADM7160ACPZN1.8  [DFN6_2X2_PAD1_6X1]  49.38 15.06 270 top
U13  MT25QU256ABA8E12-1SIT  [TBGA24]  72.11 46.81 180 top
U14  TPS51206DSQR  [SON10_2X2_PAD1_5X0_9]  41.6 57.48 0 top
U15  USB3320C-EZK  [QFN32_5X5_PAD3_3X3_3]  76.55 25.73 270 top
U16  ADP198ACBZ-11  [WLCSP4-2]  101.83 43 90 top
U17  LTC6957HMS-3#PBF  [MSOP12]  15.34 12.47 90 top
UNK1P0V  TESTPAD  [TPSMC40]  77.95 14.68 180 bottom
UNK1P3V_A  TESTPAD  [TPSMC40]  43.15 16.33 180 bottom
UNK1P3V_B  TESTPAD  [TPSMC40]  21.69 16.08 180 bottom
UNK1P8V_CLK  TESTPAD  [TPSMC40]  45.06 16.33 180 bottom
UNK1V8  TESTPAD  [TPSMC40]  94.59 9.34 180 bottom
UNK1V8#2  TESTPAD  [TPSMC40]  81.51 32.59 180 bottom
UNK1V35  TESTPAD  [TPSMC40]  80.87 55.45 180 bottom
VDD_GPO  613 001 111 21  [CNHDR1X1H344]  41.88 65.22 180 bottom
Y1  24MEGHZ  [YSML98W79H35]  77.82 33.47 270 top
Y2  33.333MEGHZ  [YSML98W79H35]  69.19 35.63 180 top
Y3  40MEGHz  [YSML126W98H47]  13.05 9.42 90 bottom

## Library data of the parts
AD9361_CLKOUT JTAG_BOOT PG_1P3V RX TCK TDI TDO TMS TX UNK1P0V UNK1P3V_A UNK1P3V_B UNK1P8V_CLK UNK1V8 UNK1V35 = NCTESTPAD: Tolerance: N/A; User Part Number: UPN; alternate symbols: (); part number: NCTESTPAD_SM-TESTPAD,E019801,TPSMC40; tolerance: N/A
ADC DAC1 DAC2 GPO0-GPO3 VDD_GPO = CN1P: User Part Number: UPN; Tolerance: N/A; alternate symbols: (); part number: CN1P_TH-613 001 111 21,E016125,CNHDR1X1H344; tolerance: N/A
C1 C5-C8 C10 C16 C18 C25 C33 C46-C48 C52 C60 C91 C92 C94-C98 C117 C118 C122 C161 C163 C164 C186 C188-C190 C201-C203 C206 C208 = CAP: Tolerance: 20; User Part Number: UPN; part number: CAP_SM-0.1UF,16V,20,E017331,C0201; tolerance: 20
C2 C12 C23 C24 C26 C27 C39-C44 C53 C61-C63 C80 C84 C99 C102 C119 C120 C162 C179 C180 C187 C191 C205 = CAP: Tolerance: 10; User Part Number: UPN; part number: CAP_SM-0.01UF,10V,10,E007201,C0201; tolerance: 10
C3 C4 C14 C15 C22 C32 C79 C82 C83 C121 C151-C153 C155 C167 = CAP: Tolerance: 20; User Part Number: UPN; alternate symbols: C0603L_ALT; part number: CAP_SM-10UF,6.3V,20,E007143,C0603; tolerance: 20
C9 C135-C138 C173 C195 C209 = CAP: Tolerance: 20; User Part Number: UPN; alternate symbols: C0603L_ALT; part number: CAP_SM-10UF,10V,20,E022682,C0603; tolerance: 20
C11 C17 C19-C21 C65 C77 C85 C103 C104 C145 C148 C184 C185 = CAP: Tolerance: 20; User Part Number: UPN; alternate symbols: (C0805L); part number: CAP_SM-47UF,6.3V,20,E008247,C0805H60; tolerance: 20
C13 = CAP: Tolerance: 20; User Part Number: UPN; alternate symbols: C0402_ALT; part number: CAP_SM-0.1UF,16V,20,E017331,C0201; tolerance: 20
C28-C31 C34-C38 C45 C127 C140 C141 C154 C168 C192 = CAP: Tolerance: 10; User Part Number: UPN; alternate symbols: C0402_ALT; part number: CAP_SM-1UF,16V,10,E025259,C0402H22; tolerance: 10
C49 C54 C64 C71 C76 C100 C149 C150 C158 = CAP: Tolerance: 20; User Part Number: UPN; part number: CAP_SM-100UF,6.3V,20,E016591,C1206H71; tolerance: 20
C50 C55 C66 C67 C73 C78 C86 C87 C101 C105-C108 C159 C174 = CAP: Tolerance: 10; User Part Number: UPN; alternate symbols: C0402_ALT; part number: CAP_SM-4.7UF,6.3V,10,E020089,C0402; tolerance: 10
C51 C56-C59 C68-C70 C72 C74 C75 C88-C90 C93 C109-C116 C160 C178 = CAP: Tolerance: 10; User Part Number: UPN; alternate symbols: C0402_ALT; part number: CAP_SM-0.47UF,10V,10,E007611,C0402; tolerance: 10
C81 = CAP: Tolerance: 10; User Part Number: UPN; part number: CAP_SM-0.22UF,25V,10,E039129,C0805H53; tolerance: 10
C123 C169 C170 C199 C200 = CAP: Tolerance: 10; User Part Number: UPN; alternate symbols: (); part number: CAP_SM-1UF,16V,10,E025259,C0402H22; tolerance: 10
C124 C130-C134 C156 C157 C175 C176 = CAP: Tolerance: 5; User Part Number: UPN; part number: CAP_SM-18PF,50V,5,E028398,C0201; tolerance: 5
C125 C128 C129 C166 C193 C194 C207 = CAP: Tolerance: 10; User Part Number: UPN; alternate symbols: (); part number: CAP_SM-0.001UF,25V,10,E006762,C0201; tolerance: 10
C126 = CAP: Tolerance: 10; User Part Number: UPN; alternate symbols: C0201_ALT; part number: CAP_SM-1UF,16V,10,E025259,C0402H22; tolerance: 10
C139 = CAP: Tolerance: 10; User Part Number: UPN; alternate symbols: C0402_ALT; part number: CAP_SM-0.047UF,25V,10,E025704,C0402; tolerance: 10
C142 = CAP: Tolerance: 1; User Part Number: UPN; alternate symbols: C0402_ALT; part number: CAP_SM-150PF,50V,1,E021911,C0402; tolerance: 1
C143 = CAP: Tolerance: 5; User Part Number: UPN; alternate symbols: C0402_ALT; part number: CAP_SM-180PF,50V,5,E033222,C0402; tolerance: 5
C144 = CAP: Tolerance: 10; User Part Number: UPN; alternate symbols: C0402_ALT; part number: CAP_SM-0.0033UF,50V,10,E007461,C0402; tolerance: 10
C146 = CAP: User Part Number: UPN; Tolerance: 10; alternate symbols: (); part number: CAP_SM-22UF,10V,10,E034225,C0805; tolerance: 10
C147 = CAP: Tolerance: 5; User Part Number: UPN; alternate symbols: C0402_ALT; part number: CAP_SM-5.6NF,50V,5,E033450,C0402H22; tolerance: 5
C165 = CAP: Tolerance: 10; User Part Number: UPN; alternate symbols: (); part number: CAP_SM-2.2UF,50V,10,E024995,C0603; tolerance: 10
C171 C172 C182 C198 C210 C215 = CAP: Tolerance: 10; User Part Number: UPN; alternate symbols: C0603L_ALT; part number: CAP_SM-2.2UF,50V,10,E024995,C0603; tolerance: 10
C177 C181 = CAP: User Part Number: UPN; Tolerance: 10; alternate symbols: (C0603L); part number: CAP_SM-0.1UF,100V,10,E033337,C0603; tolerance: 10
C183 C211-C214 = CAP: Tolerance: 10; User Part Number: UPN; alternate symbols: (C0603L); part number: CAP_SM-0.1UF,100V,10,E033337,C0603; tolerance: 10
C196 C197 C204 = CAP: User Part Number: UPN; Tolerance: 5; alternate symbols: (); part number: CAP_SM-47PF,50V,5,E011821,C0402; tolerance: 5
CLK_IN CLK_OUT RX2A TX2A = CNBNC3P: Tolerance: N/A; User Part Number: UPN; alternate symbols: (); part number: CNBNC3P_SM-U.FL-R-SMT-1(01),E022198,CNHIROSE-U_FL-R-SMT-1; tolerance: N/A
D1 D2 = DIOTVS6P_V2: User Part Number: UPN; Tolerance: N/A; alternate symbols: (); part number: DIOTVS6P_V2_SM-SP3004-04XTG,6V,N/A,E026047,SOT-563; tolerance: N/A
D3 D4 D7-D10 = DIOZNR_V2: User Part Number: UPN; Tolerance: N/A; alternate symbols: (); part number: DIOZNR_V2_SM-ESD8472MUT5G,N/A,N/A,E034844,DFN2_0_62X0_32; tolerance: N/A
DS1 DS2 = DIOLED: User Part Number: UPN; Tolerance: N/A; alternate symbols: LED0804_RA; part number: DIOLED_SM-LTST-S220TBKT,3.3V,N/A,E026167,LED0804; tolerance: N/A
E1 E2 E4-E8 = FERRITE: User Part Number: UPN; Tolerance: 25; alternate symbols: (); part number: FERRITE_SM-100OHM,25,E012241,L0805; tolerance: 25
E3 E9-E11 = FERRITE: User Part Number: UPN; Tolerance: 25; alternate symbols: (); part number: FERRITE_SM-600OHM AT 100MEGHZ,25,E022193,L0805; tolerance: 25
F1 = FSFUSE: User Part Number: UPN; Tolerance: N/A; alternate symbols: (); part number: FSFUSE_SM-0.5A,6V,E023876,F0402H20; tolerance: N/A
GND = -: User Part Number: UPN; Tolerance: N/A
GND#2-GND#4 UNK1V8#2 = -: Tolerance: N/A; User Part Number: UPN
L1 L7-L9 = IND: Tolerance: 5; User Part Number: UPN; part number: IND_SM-330NH,5,E006599,L0805-F; tolerance: 5
L2 L3 = IND: User Part Number: UPN; Tolerance: 20; alternate symbols: (); part number: IND_SM-1.5UH,20,E017267,LSMSQ157H83; tolerance: 20
L4 = IND: User Part Number: UPN; Tolerance: 20; alternate symbols: (); part number: IND_SM-1UH,20,E015845,LSMSQ157H83; tolerance: 20
L5 = IND: User Part Number: UPN; Tolerance: 20; alternate symbols: (); part number: IND_SM-270NH,20,E027278,LSMSQ79H41; tolerance: 20
L6 = CHOKE4P: User Part Number: UPN; Tolerance: 25; alternate symbols: (); part number: CHOKE4P_SM-90OHMS AT 100MEGHZ,25,E027226,L0805-4PH39; tolerance: 25
L7N L9N L10P L12N L24N MIO0 MIO09-MIO11 MIO48 MIO49 MIO53 = NCWP: Tolerance: N/A; User Part Number: UPN; alternate symbols: (); part number: NCWP_TH-WP45,E002516,TPC75D45; tolerance: N/A
L10 = CHOKE4P: User Part Number: UPN; Tolerance: N/A; alternate symbols: (); part number: CHOKE4P_SM-800OHMS AT 100MEGHZ,N/A,E027130,L2020_A; tolerance: N/A
P1 = CN10P_ODD_EVEN: Tolerance: N/A; User Part Number: UPN; part number: CN10P_ODD_EVEN_TH-FTSH-105-01-L-D,E018623,CNHDR2X5H219; tolerance: N/A
P2 P3 = CN5P_3SHLD: User Part Number: UPN; Tolerance: N/A; alternate symbols: (); part number: CN5P_3SHLD_SM-47590-0001,E015753,CNMOLEX47590-0001; tolerance: N/A
Q1-Q4 = TRANNMOSFET_V8: User Part Number: UPN; Tolerance: N/A; part number: TRANNMOSFET_V8_SM-BSS138LT1G,E018770,SOT23; tolerance: N/A
R1 R56 = RES: User Part Number: UPN; Tolerance: 1; part number: RES_SM-10,E013982,1/20W,1,R0201; tolerance: 1
R2 R53 = RES: Tolerance: 1; User Part Number: UPN; alternate symbols: R0402_ALT; part number: RES_SM-27.4K,E021819,1/10W,1,R0402; tolerance: 1
R3 R64 = RES: Tolerance: 1; User Part Number: UPN; alternate symbols: R0402_ALT; part number: RES_SM-46.4K,E011115,1/16W,1,R0402; tolerance: 1
R4 = RES: Tolerance: 1; User Part Number: UPN; alternate symbols: R0603_A; part number: RES_SM-17.8K,E011033,1/10W,1,R0603; tolerance: 1
R5 = RES: Tolerance: 1; User Part Number: UPN; alternate symbols: (R0402L,R0402L_ALT); part number: RES_SM-1K,E003763,1/10W,1,R0402; tolerance: 1
R6 R8 R60 R61 R74 R75 R92-R94 R107 R221 R222 = RES: Tolerance: 1; User Part Number: UPN; alternate symbols: R0402_ALT; part number: RES_SM-10K,E003751,1/10W,1,R0402; tolerance: 1
R7 R42 = RES: Tolerance: 1; User Part Number: UPN; alternate symbols: R0402_ALT; part number: RES_SM-1K,E003763,1/10W,1,R0402; tolerance: 1
R9 = RES: User Part Number: UPN; Tolerance: 1; part number: RES_SM-10K,E004011,1/20W,1,R0201; tolerance: 1
R10 R69 R104 = RES: User Part Number: UPN; Tolerance: N/A; alternate symbols: (); part number: RES_SM-0,E004015,1/20W,0,R0201; tolerance: N/A
R11 R46 R47 R54 R80 R85 R89 R91 = RES: Tolerance: 1; User Part Number: UPN; alternate symbols: R0402_ALT; part number: RES_SM-4.7K,E008190,1/10W,1,R0402; tolerance: 1
R12 R82 = RES: Tolerance: 5; User Part Number: UPN; alternate symbols: R0402_ALT; part number: RES_SM-39,E003441,1/16W,5,R0402; tolerance: 5
R13 R57 R76 R83 R84 R116 R119-R122 = RES: Tolerance: 1; User Part Number: UPN; alternate symbols: R0402_ALT; part number: RES_SM-20K,E003791,1/16W,1,R0402; tolerance: 1
R14 R40 R41 R86 R99 R165 = RES: Tolerance: 1; User Part Number: UPN; alternate symbols: R0402_ALT; part number: RES_SM-240,E010877,1/16W,1,R0402; tolerance: 1
R15 R43-R45 = RES: Tolerance: 1; User Part Number: UPN; alternate symbols: R0402_ALT; part number: RES_SM-0,E010661,1/16W,1,R0402; tolerance: 1
R16-R39 = RES: User Part Number: UPN; Tolerance: 1; part number: RES_SM-120,E011549,1/20W,1,R0201; tolerance: 1
R48 R87 = RES: Tolerance: 5; User Part Number: UPN; alternate symbols: R0402_ALT; part number: RES_SM-470,E017765,1/10W,5,R0402; tolerance: 5
R49 R63 = RES: User Part Number: UPN; Tolerance: 1; part number: RES_SM-14.3K,E014068,1/20W,1,R0201; tolerance: 1
R50 R59 = RES: Tolerance: 1; User Part Number: UPN; alternate symbols: R0402_ALT; part number: RES_SM-100K,E003796,1/16W,1,R0402; tolerance: 1
R51 R52 = RES: User Part Number: UPN; part number: RES_SM-1,E014056,1/20W,1,R0201
R55 R58 = RES: User Part Number: UPN; Tolerance: 1; alternate symbols: (R0805L); part number: RES_SM-1K,E023448,1/3W,1,R0805; tolerance: 1
R62 = RES: Tolerance: 1; User Part Number: UPN; alternate symbols: R0603L; part number: RES_SM-17.8K,E011033,1/10W,1,R0603; tolerance: 1
R65 = RES: Tolerance: 1; User Part Number: UPN; alternate symbols: R0402_ALT; part number: RES_SM-23.2K,E036030,1/10W,1,R0402; tolerance: 1
R66 = RES: Tolerance: 1; User Part Number: UPN; alternate symbols: (R0402L,R0402L_ALT); part number: RES_SM-20K,E003791,1/16W,1,R0402; tolerance: 1
R67 = RES: User Part Number: UPN; Tolerance: 1; alternate symbols: (R0402L,R0402L_ALT); part number: RES_SM-1K,E003763,1/10W,1,R0402; tolerance: 1
R68 R97 R101 R103 = RES: Tolerance: 1; User Part Number: UPN; alternate symbols: R0402_ALT; part number: RES_SM-2.2K,E041039,1/16W,1,R0402; tolerance: 1
R70 = RES: Tolerance: 1; User Part Number: UPN; alternate symbols: R0402L_ALT; part number: RES_SM-27.4K,E021819,1/10W,1,R0402; tolerance: 1
R71 = RES: Tolerance: 1; User Part Number: UPN; alternate symbols: R0402L_ALT; part number: RES_SM-100,E016329,1/10W,1,R0402; tolerance: 1
R72 = RES: Tolerance: 1; User Part Number: UPN; alternate symbols: R0402L_ALT; part number: RES_SM-8.06K,E021385,1/10W,1,R0402; tolerance: 1
R73 R78 = RES: Tolerance: 1; User Part Number: UPN; alternate symbols: R0402L_ALT; part number: RES_SM-470,E014032,1/16W,1,R0402; tolerance: 1
R77 = RES: Tolerance: 1; User Part Number: UPN; alternate symbols: R0402_ALT; part number: RES_SM-8.06K,E021385,1/10W,1,R0402; tolerance: 1
R79 R81 R95 R102 = RES: Tolerance: 5; User Part Number: UPN; alternate symbols: (R0402L); part number: RES_SM-39,E003441,1/16W,5,R0402; tolerance: 5
R88 = RES: Tolerance: 1; User Part Number: UPN; alternate symbols: (R0402L); part number: RES_SM-24.9K,E007443,1/16W,1,R0402; tolerance: 1
R90 = RES: Tolerance: 1; User Part Number: UPN; alternate symbols: (R0402L,R0402L_ALT); part number: RES_SM-4.7K,E008190,1/10W,1,R0402; tolerance: 1
R96 = RES: Tolerance: 0.1; User Part Number: UPN; alternate symbols: (); part number: RES_SM-49.9,E030840,1/2W,0.1,R0603H18; tolerance: 0.1
R98 = RES: Tolerance: 1; User Part Number: UPN; alternate symbols: (R0402L); part number: RES_SM-75,E003748,1/16W,1,R0402; tolerance: 1
R100 = RES: Tolerance: 1; User Part Number: UPN; alternate symbols: (R0402L); part number: RES_SM-100,E016329,1/10W,1,R0402; tolerance: 1
R142 = RES: Tolerance: 0.1; User Part Number: UPN; alternate symbols: R0402_ALT; part number: RES_SM-80.6,E022369,1/16W,0.1,R0402; tolerance: 0.1
RX1A TX1A = CNBNC5P: User Part Number: UPN; Tolerance: N/A; alternate symbols: (); part number: CNBNC5P_SM-JCCEM001,E027545,CNSMARAL687W375H171; tolerance: N/A
S1 = SWSPST5P_V2: User Part Number: UPN; Tolerance: N/A; alternate symbols: (); part number: SWSPST5P_V2_SM-PTS840 GKP SMTR LFS,E024294,SWSML140W138H55; tolerance: N/A
T1-T3 T5 = XFMRTCMXXXX_V3: Tolerance: N/A; User Part Number: UPN; part number: XFMRTCMXXXX_V3_SM-TCM1-63AX+,E018203,TSML150W160H160; tolerance: N/A
U1 U7 = ADP1754: Tolerance: N/A; User Part Number: UPN; alternate symbols: (); part number: ADP1754_SM-ADP1754ACPZ-1.3,E022696,QFN16_4X4_PAD2_1X2_1; tolerance: N/A
U2 = ICMT41K256M16: User Part Number: UPN; Tolerance: N/A; alternate symbols: (); part number: ICMT41K256M16_SM-MT41K256M16TW-107 IT:P,E025601,FBGA96_C; tolerance: N/A
U3 = ADP2164: Tolerance: N/A; User Part Number: UPN; alternate symbols: (); part number: ADP2164_SM-ADP2164ACPZ,E013699,QFN16_4X4_PAD2_5X2_5; tolerance: N/A
U4 = ICXC7Z010: Tolerance: N/A; User Part Number: UPN; alternate symbols: (); part number: ICXC7Z010_SM-XC7Z010-1CLG225C4334,E025809,CSPBGA225; tolerance: N/A
U5 = AD9363: Tolerance: N/A; User Part Number: UPN; part number: AD9363_SM-AD9363ABCZ,E026056,BGA144-2; tolerance: N/A
U6 = ADP2114: User Part Number: UPN; Tolerance: N/A; alternate symbols: (); part number: ADP2114_SM-ADP2114ACPZ,E008105,QFN32_5X5_PAD3_1X3_1; tolerance: N/A
U8 = LINLTC4415: User Part Number: UPN; Tolerance: N/A; alternate symbols: (); part number: LINLTC4415_SM-LTC4415EDHC#PBF,E027541,DFN16_5X3_PAD4_4X1_65; tolerance: N/A
U9 = ICFT230XQ: Tolerance: N/A; User Part Number: UPN; alternate symbols: (); part number: ICFT230XQ_SM-FT230XQ-R,E021729,QFN16_4X4_PAD2_1X2_1; tolerance: N/A
U10 = 741G126: User Part Number: UPN; Tolerance: N/A; alternate symbols: (); part number: 741G126_SM-74LVC1G126GW,E017822,SOT353; tolerance: N/A
U11 = ADM7160_V2: User Part Number: UPN; Tolerance: N/A; alternate symbols: (); part number: ADM7160_V2_SM-ADM7160ACPZN3.3,E018695,DFN6_2X2_PAD1_6X1; tolerance: N/A
U12 = ADM7160_V2: User Part Number: UPN; Tolerance: N/A; alternate symbols: (); part number: ADM7160_V2_SM-ADM7160ACPZN1.8,E018693,DFN6_2X2_PAD1_6X1; tolerance: N/A
U13 = ICMT25Q: User Part Number: UPN; Tolerance: N/A; alternate symbols: (); part number: ICMT25Q_SM-MT25QU256ABA8E12-1SIT,E027529,TBGA24; tolerance: N/A
U14 = ICTPS51206: Tolerance: N/A; User Part Number: UPN; alternate symbols: (); part number: ICTPS51206_SM-TPS51206DSQR,E021346,SON10_2X2_PAD1_5X0_9; tolerance: N/A
U15 = ICUSB3320C: Tolerance: N/A; User Part Number: UPN; alternate symbols: (); part number: ICUSB3320C_SM-USB3320C-EZK,E021334,QFN32_5X5_PAD3_3X3_3; tolerance: N/A
U16 = ADP198: Tolerance: N/A; User Part Number: UPN; alternate symbols: (); part number: ADP198_SM-ADP198ACBZ-11,E024730,WLCSP4-2; tolerance: N/A
U17 = ICLTC6957_V3: User Part Number: UPN; Tolerance: N/A; alternate symbols: (); part number: ICLTC6957_V3_SM-LTC6957HMS-3#PBF,E030596,MSOP12; tolerance: N/A
Y1 = XTALOSC4P_V7: Tolerance: N/A; User Part Number: UPN; alternate symbols: (); part number: XTALOSC4P_V7_SM-24MEGHZ,E022374,YSML98W79H35; tolerance: N/A
Y2 = XTALOSC4P_V7: Tolerance: N/A; User Part Number: UPN; part number: XTALOSC4P_V7_SM-33.333MEGHZ,E024048,YSML98W79H35; tolerance: N/A
Y3 = XTALOSC4P_V21: Tolerance: N/A; User Part Number: UPN; part number: XTALOSC4P_V21_SM-40MEGHZ,E020493,YSML126W98H47; tolerance: N/A

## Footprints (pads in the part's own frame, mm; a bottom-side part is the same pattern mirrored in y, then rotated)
BGA144-2
  round 0.356 smd: A1(-4.4,-4.4) A2(-4.4,-3.6) A3(-4.4,-2.8) A4(-4.4,-2) A5(-4.4,-1.2) A6(-4.4,-0.4) A7(-4.4,0.4) A8(-4.4,1.2) A9(-4.4,2) A10(-4.4,2.8) A11(-4.4,3.6) A12(-4.4,4.4) B1(-3.6,-4.4) B2(-3.6,-3.6) B3(-3.6,-2.8) B4(-3.6,-2) B5(-3.6,-1.2) B6(-3.6,-0.4) B7(-3.6,0.4) B8(-3.6,1.2) B9(-3.6,2) B10(-3.6,2.8) B11(-3.6,3.6) B12(-3.6,4.4) C1(-2.8,-4.4) C2(-2.8,-3.6) C3(-2.8,-2.8) C4(-2.8,-2) C5(-2.8,-1.2) C6(-2.8,-0.4) C7(-2.8,0.4) C8(-2.8,1.2) C9(-2.8,2) C10(-2.8,2.8) C11(-2.8,3.6) C12(-2.8,4.4) D1(-2,-4.4) D2(-2,-3.6) D3(-2,-2.8) D4(-2,-2) D5(-2,-1.2) D6(-2,-0.4) D7(-2,0.4) D8(-2,1.2) D9(-2,2) D10(-2,2.8) D11(-2,3.6) D12(-2,4.4) E1(-1.2,-4.4) E2(-1.2,-3.6) E3(-1.2,-2.8) E4(-1.2,-2) E5(-1.2,-1.2) E6(-1.2,-0.4) E7(-1.2,0.4) E8(-1.2,1.2) E9(-1.2,2) E10(-1.2,2.8) E11(-1.2,3.6) E12(-1.2,4.4) F1(-0.4,-4.4) F2(-0.4,-3.6) F3(-0.4,-2.8) F4(-0.4,-2) F5(-0.4,-1.2) F6(-0.4,-0.4) F7(-0.4,0.4) F8(-0.4,1.2) F9(-0.4,2) F10(-0.4,2.8) F11(-0.4,3.6) F12(-0.4,4.4) G1(0.4,-4.4) G2(0.4,-3.6) G3(0.4,-2.8) G4(0.4,-2) G5(0.4,-1.2) G6(0.4,-0.4) G7(0.4,0.4) G8(0.4,1.2) G9(0.4,2) G10(0.4,2.8) G11(0.4,3.6) G12(0.4,4.4) H1(1.2,-4.4) H2(1.2,-3.6) H3(1.2,-2.8) H4(1.2,-2) H5(1.2,-1.2) H6(1.2,-0.4) H7(1.2,0.4) H8(1.2,1.2) H9(1.2,2) H10(1.2,2.8) H11(1.2,3.6) H12(1.2,4.4) J1(2,-4.4) J2(2,-3.6) J3(2,-2.8) J4(2,-2) J5(2,-1.2) J6(2,-0.4) J7(2,0.4) J8(2,1.2) J9(2,2) J10(2,2.8) J11(2,3.6) J12(2,4.4) K1(2.8,-4.4) K2(2.8,-3.6) K3(2.8,-2.8) K4(2.8,-2) K5(2.8,-1.2) K6(2.8,-0.4) K7(2.8,0.4) K8(2.8,1.2) K9(2.8,2) K10(2.8,2.8) K11(2.8,3.6) K12(2.8,4.4) L1(3.6,-4.4) L2(3.6,-3.6) L3(3.6,-2.8) L4(3.6,-2) L5(3.6,-1.2) L6(3.6,-0.4) L7(3.6,0.4) L8(3.6,1.2) L9(3.6,2) L10(3.6,2.8) L11(3.6,3.6) L12(3.6,4.4) M1(4.4,-4.4) M2(4.4,-3.6) M3(4.4,-2.8) M4(4.4,-2) M5(4.4,-1.2) M6(4.4,-0.4) M7(4.4,0.4) M8(4.4,1.2) M9(4.4,2) M10(4.4,2.8) M11(4.4,3.6) M12(4.4,4.4)
C0201
  rect 0.305x0.406 smd: 1(-0.318,0) 2(0.318,0)
C0201#2
  rect 0.61x0.61 smd: 1(-0.495,0) 2(0.495,0)
C0402
  rect 0.61x0.61 smd: 1(-0.495,0) 2(0.495,0)
C0402H22
  rect 0.61x0.61 smd: 1(-0.495,0) 2(0.495,0)
C0603
  rect 0.762x0.889 smd: 1(-0.699,0) 2(0.699,0)
C0603#2
  rect 1.092x1.194 smd: 1(-0.851,0) 2(0.851,0)
C0805
  rect 1.143x1.448 smd: 1(-0.9,0) 2(0.9,0)
C0805H53
  rect 1.295x1.6 smd: 1(-0.953,0) 2(0.953,0)
C0805H60
  rect 1.295x1.6 smd: 1(-0.953,0) 2(0.953,0)
C1206H71
  rect 1.6x2.007 smd: 1(-1.397,0) 2(1.397,0)
CNHDR1X1H344
  round 1.651 hole 1.143: 1(0,0)
CNHDR2X5H219
  rect 1.067x1.067 hole 0.711: 1(0,0)
  round 1.067 hole 0.711: 2(0,1.27) 3(1.27,0) 4(1.27,1.27) 5(2.54,0) 6(2.54,1.27) 7(3.81,0) 8(3.81,1.27) 9(5.08,0) 10(5.08,1.27)
CNHIROSE-U_FL-R-SMT-1
  rect 0.991x1.041 smd: 1(0,-1.521)
  rect 1.041x2.21 smd: 2(-1.471,0) 3(1.471,0)
CNMOLEX47590-0001
  oval 1.118x0.914 hole 0.864x0.66: (4.45,2.225) (4.45,-2.225)
  rect 1.346x0.406 smd: 1(4.123,-1.3) 2(4.123,-0.65) 3(4.123,0) 4(4.123,0.65) 5(4.123,1.3)
  custom 0.349x0.349 hole 1.295x0.61: SH1(1.45,4.175) SH3(1.45,-4.175)
  rect 1.905x2.896 smd: SH2(1.45,0)
CNSMARAL687W375H171
  rect 5.08x0.483 smd: 1(-0.254,0)
  rect 5.08x2.413 smd: 2(-0.254,4.381) 3(-0.254,4.381) 4(-0.254,-4.381) 5(-0.254,-4.381)
CSPBGA225
  round 0.305 smd: A1(-5.6,-5.6) A2(-5.6,-4.8) A3(-5.6,-4) A4(-5.6,-3.2) A5(-5.6,-2.4) A6(-5.6,-1.6) A7(-5.6,-0.8) A8(-5.6,0) A9(-5.6,0.8) A10(-5.6,1.6) A11(-5.6,2.4) A12(-5.6,3.2) A13(-5.6,4) A14(-5.6,4.8) A15(-5.6,5.6) B1(-4.8,-5.6) B2(-4.8,-4.8) B3(-4.8,-4) B4(-4.8,-3.2) B5(-4.8,-2.4) B6(-4.8,-1.6) B7(-4.8,-0.8) B8(-4.8,0) B9(-4.8,0.8) B10(-4.8,1.6) B11(-4.8,2.4) B12(-4.8,3.2) B13(-4.8,4) B14(-4.8,4.8) B15(-4.8,5.6) C1(-4,-5.6) C2(-4,-4.8) C3(-4,-4) C4(-4,-3.2) C5(-4,-2.4) C6(-4,-1.6) C7(-4,-0.8) C8(-4,0) C9(-4,0.8) C10(-4,1.6) C11(-4,2.4) C12(-4,3.2) C13(-4,4) C14(-4,4.8) C15(-4,5.6) D1(-3.2,-5.6) D2(-3.2,-4.8) D3(-3.2,-4) D4(-3.2,-3.2) D5(-3.2,-2.4) D6(-3.2,-1.6) D7(-3.2,-0.8) D8(-3.2,0) D9(-3.2,0.8) D10(-3.2,1.6) D11(-3.2,2.4) D12(-3.2,3.2) D13(-3.2,4) D14(-3.2,4.8) D15(-3.2,5.6) E1(-2.4,-5.6) E2(-2.4,-4.8) E3(-2.4,-4) E4(-2.4,-3.2) E5(-2.4,-2.4) E6(-2.4,-1.6) E7(-2.4,-0.8) E8(-2.4,0) E9(-2.4,0.8) E10(-2.4,1.6) E11(-2.4,2.4) E12(-2.4,3.2) E13(-2.4,4) E14(-2.4,4.8) E15(-2.4,5.6) F1(-1.6,-5.6) F2(-1.6,-4.8) F3(-1.6,-4) F4(-1.6,-3.2) F5(-1.6,-2.4) F6(-1.6,-1.6) F7(-1.6,-0.8) F8(-1.6,0) F9(-1.6,0.8) F10(-1.6,1.6) F11(-1.6,2.4) F12(-1.6,3.2) F13(-1.6,4) F14(-1.6,4.8) F15(-1.6,5.6) G1(-0.8,-5.6) G2(-0.8,-4.8) G3(-0.8,-4) G4(-0.8,-3.2) G5(-0.8,-2.4) G6(-0.8,-1.6) G7(-0.8,-0.8) G8(-0.8,0) G9(-0.8,0.8) G10(-0.8,1.6) G11(-0.8,2.4) G12(-0.8,3.2) G13(-0.8,4) G14(-0.8,4.8) G15(-0.8,5.6) H1(0,-5.6) H2(0,-4.8) H3(0,-4) H4(0,-3.2) H5(0,-2.4) H6(0,-1.6) H7(0,-0.8) H8(0,0) H9(0,0.8) H10(0,1.6) H11(0,2.4) H12(0,3.2) H13(0,4) H14(0,4.8) H15(0,5.6) J1(0.8,-5.6) J2(0.8,-4.8) J3(0.8,-4) J4(0.8,-3.2) J5(0.8,-2.4) J6(0.8,-1.6) J7(0.8,-0.8) J8(0.8,0) J9(0.8,0.8) J10(0.8,1.6) J11(0.8,2.4) J12(0.8,3.2) J13(0.8,4) J14(0.8,4.8) J15(0.8,5.6) K1(1.6,-5.6) K2(1.6,-4.8) K3(1.6,-4) K4(1.6,-3.2) K5(1.6,-2.4) K6(1.6,-1.6) K7(1.6,-0.8) K8(1.6,0) K9(1.6,0.8) K10(1.6,1.6) K11(1.6,2.4) K12(1.6,3.2) K13(1.6,4) K14(1.6,4.8) K15(1.6,5.6) L1(2.4,-5.6) L2(2.4,-4.8) L3(2.4,-4) L4(2.4,-3.2) L5(2.4,-2.4) L6(2.4,-1.6) L7(2.4,-0.8) L8(2.4,0) L9(2.4,0.8) L10(2.4,1.6) L11(2.4,2.4) L12(2.4,3.2) L13(2.4,4) L14(2.4,4.8) L15(2.4,5.6) M1(3.2,-5.6) M2(3.2,-4.8) M3(3.2,-4) M4(3.2,-3.2) M5(3.2,-2.4) M6(3.2,-1.6) M7(3.2,-0.8) M8(3.2,0) M9(3.2,0.8) M10(3.2,1.6) M11(3.2,2.4) M12(3.2,3.2) M13(3.2,4) M14(3.2,4.8) M15(3.2,5.6) N1(4,-5.6) N2(4,-4.8) N3(4,-4) N4(4,-3.2) N5(4,-2.4) N6(4,-1.6) N7(4,-0.8) N8(4,0) N9(4,0.8) N10(4,1.6) N11(4,2.4) N12(4,3.2) N13(4,4) N14(4,4.8) N15(4,5.6) P1(4.8,-5.6) P2(4.8,-4.8) P3(4.8,-4) P4(4.8,-3.2) P5(4.8,-2.4) P6(4.8,-1.6) P7(4.8,-0.8) P8(4.8,0) P9(4.8,0.8) P10(4.8,1.6) P11(4.8,2.4) P12(4.8,3.2) P13(4.8,4) P14(4.8,4.8) P15(4.8,5.6) R1(5.6,-5.6) R2(5.6,-4.8) R3(5.6,-4) R4(5.6,-3.2) R5(5.6,-2.4) R6(5.6,-1.6) R7(5.6,-0.8) R8(5.6,0) R9(5.6,0.8) R10(5.6,1.6) R11(5.6,2.4) R12(5.6,3.2) R13(5.6,4) R14(5.6,4.8) R15(5.6,5.6)
DFN2_0_62X0_32
  rect 0.305x0.305 smd: 1(-0.218,0) 2(0.218,0)
DFN6_2X2_PAD1_6X1
  oval 0.305x0.864 smd: 1(-0.65,-1.082) 2(0,-1.082) 3(0.65,-1.082) 4(0.65,1.082) 5(0,1.082) 6(-0.65,1.082)
  rect 1.6x0.991 smd: PAD(0,0)
DFN16_5X3_PAD4_4X1_65
  custom 0.165x0.165 smd: 1(-1.75,-1.43) 7(1.25,-1.43) 9(1.75,1.43) 15(-1.25,1.43)
  round 0.127 smd: 2(-1.25,-1.43) 8(1.75,-1.43) 10(1.25,1.43) 16(-1.75,1.43)
  rect 0.305x0.66 smd: 3(-0.75,-1.43) 4(-0.25,-1.43) 5(0.25,-1.43) 6(0.75,-1.43) 11(0.75,1.43) 12(0.25,1.43) 13(-0.25,1.43) 14(-0.75,1.43)
  rect 4.394x1.651 smd: PAD(0,0)
F0402H20
  rect 0.559x0.711 smd: 1(-0.49,0) 2(0.49,0)
FBGA96_C
  round 0.381 smd: A1(-6,-3.2) A2(-6,-2.4) A3(-6,-1.6) A7(-6,1.6) A8(-6,2.4) A9(-6,3.2) B1(-5.2,-3.2) B2(-5.2,-2.4) B3(-5.2,-1.6) B7(-5.2,1.6) B8(-5.2,2.4) B9(-5.2,3.2) C1(-4.4,-3.2) C2(-4.4,-2.4) C3(-4.4,-1.6) C7(-4.4,1.6) C8(-4.4,2.4) C9(-4.4,3.2) D1(-3.6,-3.2) D2(-3.6,-2.4) D3(-3.6,-1.6) D7(-3.6,1.6) D8(-3.6,2.4) D9(-3.6,3.2) E1(-2.8,-3.2) E2(-2.8,-2.4) E3(-2.8,-1.6) E7(-2.8,1.6) E8(-2.8,2.4) E9(-2.8,3.2) F1(-2,-3.2) F2(-2,-2.4) F3(-2,-1.6) F7(-2,1.6) F8(-2,2.4) F9(-2,3.2) G1(-1.2,-3.2) G2(-1.2,-2.4) G3(-1.2,-1.6) G7(-1.2,1.6) G8(-1.2,2.4) G9(-1.2,3.2) H1(-0.4,-3.2) H2(-0.4,-2.4) H3(-0.4,-1.6) H7(-0.4,1.6) H8(-0.4,2.4) H9(-0.4,3.2) J1(0.4,-3.2) J2(0.4,-2.4) J3(0.4,-1.6) J7(0.4,1.6) J8(0.4,2.4) J9(0.4,3.2) K1(1.2,-3.2) K2(1.2,-2.4) K3(1.2,-1.6) K7(1.2,1.6) K8(1.2,2.4) K9(1.2,3.2) L1(2,-3.2) L2(2,-2.4) L3(2,-1.6) L7(2,1.6) L8(2,2.4) L9(2,3.2) M1(2.8,-3.2) M2(2.8,-2.4) M3(2.8,-1.6) M7(2.8,1.6) M8(2.8,2.4) M9(2.8,3.2) N1(3.6,-3.2) N2(3.6,-2.4) N3(3.6,-1.6) N7(3.6,1.6) N8(3.6,2.4) N9(3.6,3.2) P1(4.4,-3.2) P2(4.4,-2.4) P3(4.4,-1.6) P7(4.4,1.6) P8(4.4,2.4) P9(4.4,3.2) R1(5.2,-3.2) R2(5.2,-2.4) R3(5.2,-1.6) R7(5.2,1.6) R8(5.2,2.4) R9(5.2,3.2) T1(6,-3.2) T2(6,-2.4) T3(6,-1.6) T7(6,1.6) T8(6,2.4) T9(6,3.2)
